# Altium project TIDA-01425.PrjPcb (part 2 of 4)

## Sheet DIG PWR.SchDoc: DIG PWR
size 558 x 431 mm; Date: Not shown in title block; ApprovedBy: Not shown in title block; CheckedBy: Not shown in title block; Author: Not shown in title block; CompanyName: Not shown in title block; DrawnBy: Donovan Porter; Engineer: Not shown in title block; Organization: Not shown in title block; Address1: Not shown in title block; Address2: Not shown in title block; Address3: Not shown in title block; Address4: Not shown in title block; DocumentNumber: 5; Revision: Use project parameter SCH_Rev; SheetNumber: 5; SheetTotal: 12; PageSetup: Record=PageOptions¦CenterHorizontal=True¦CenterVertical=True¦PrintScale=1.00¦XCorrection=1.00¦YCorrection=1.00¦PrintKind=0¦BorderSize=5000000¦LeftOffset=0¦BottomOffset=0¦Orientation=2¦PaperLength=1000¦PaperWidth=1000¦Scale=100¦PaperSource=15¦PrintQuality=600¦MediaType=1¦DitherType=10¦PaperKind=Letter¦PrintScaleMode=1
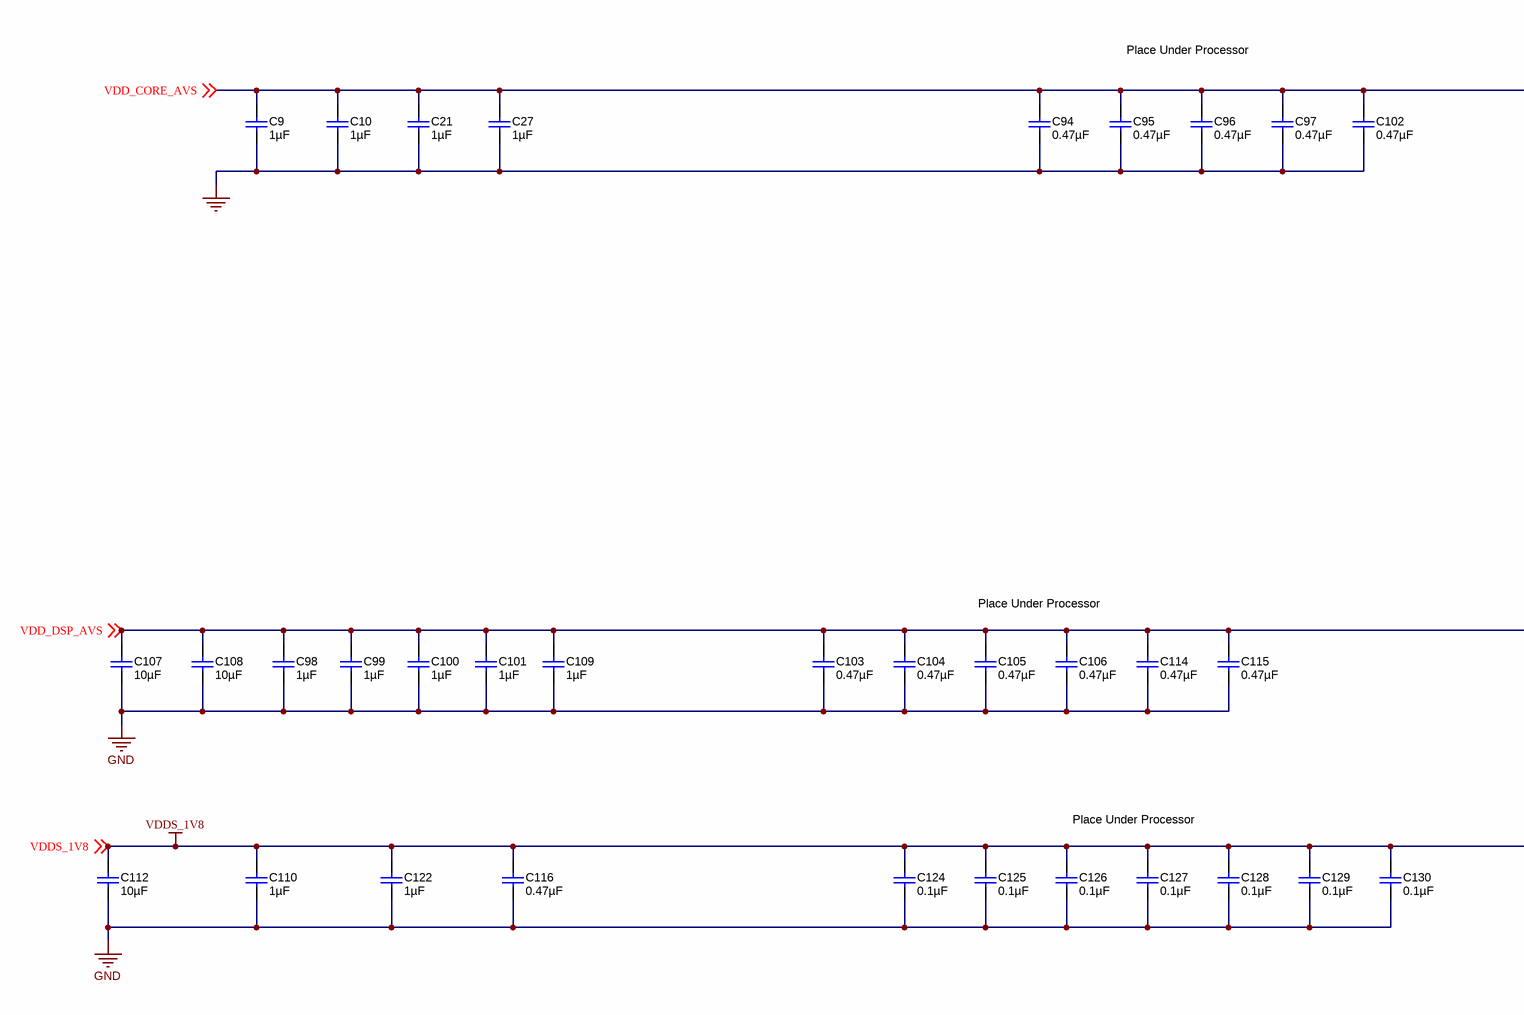
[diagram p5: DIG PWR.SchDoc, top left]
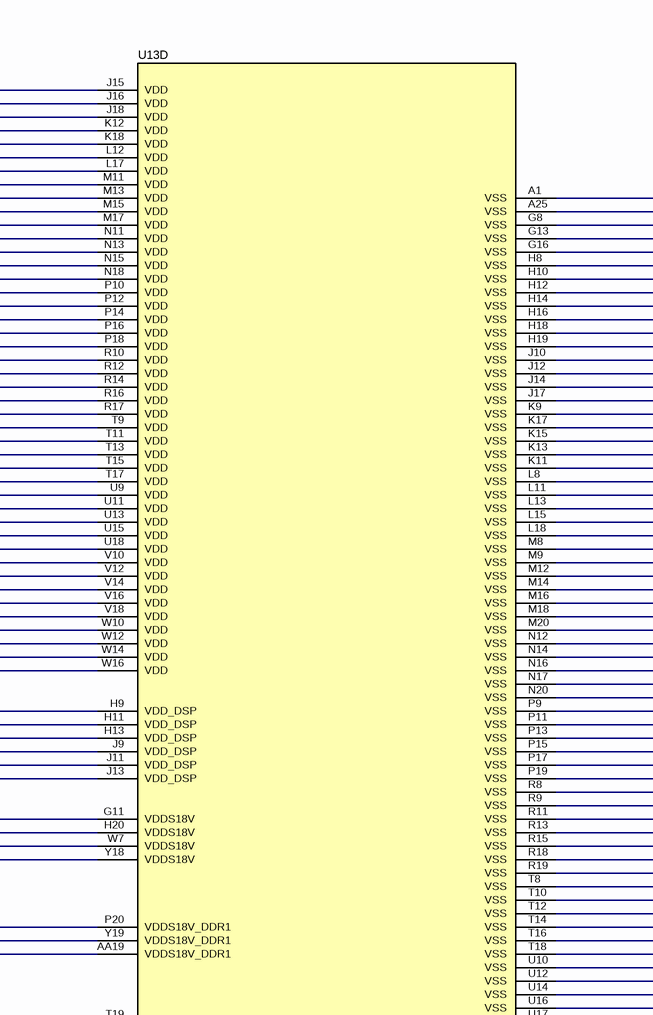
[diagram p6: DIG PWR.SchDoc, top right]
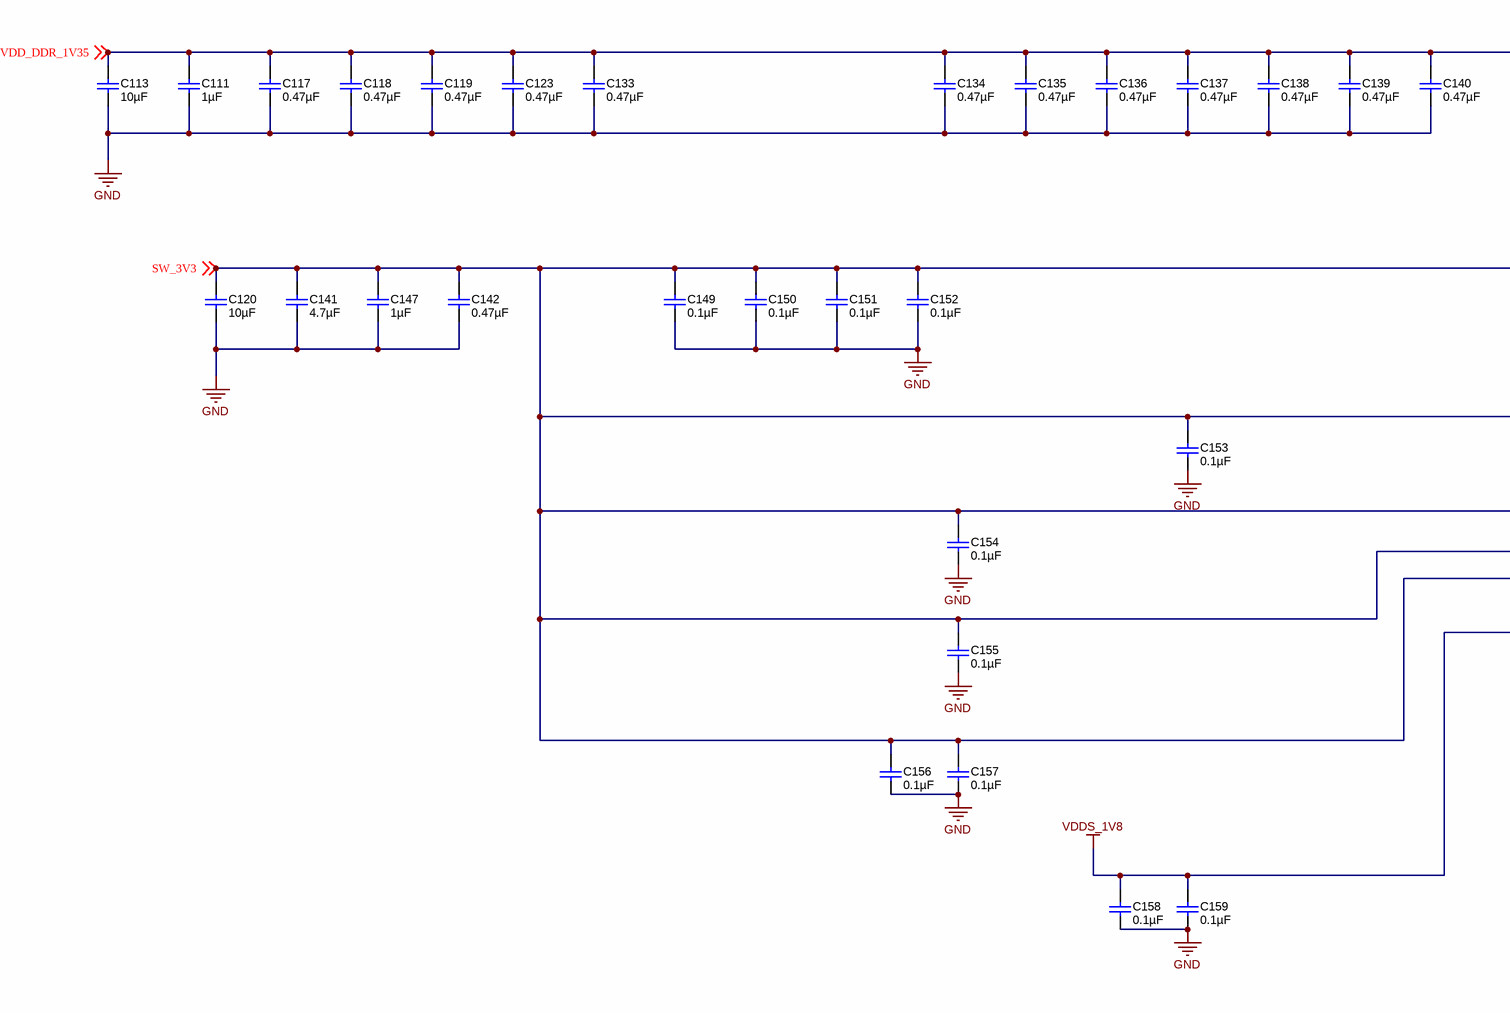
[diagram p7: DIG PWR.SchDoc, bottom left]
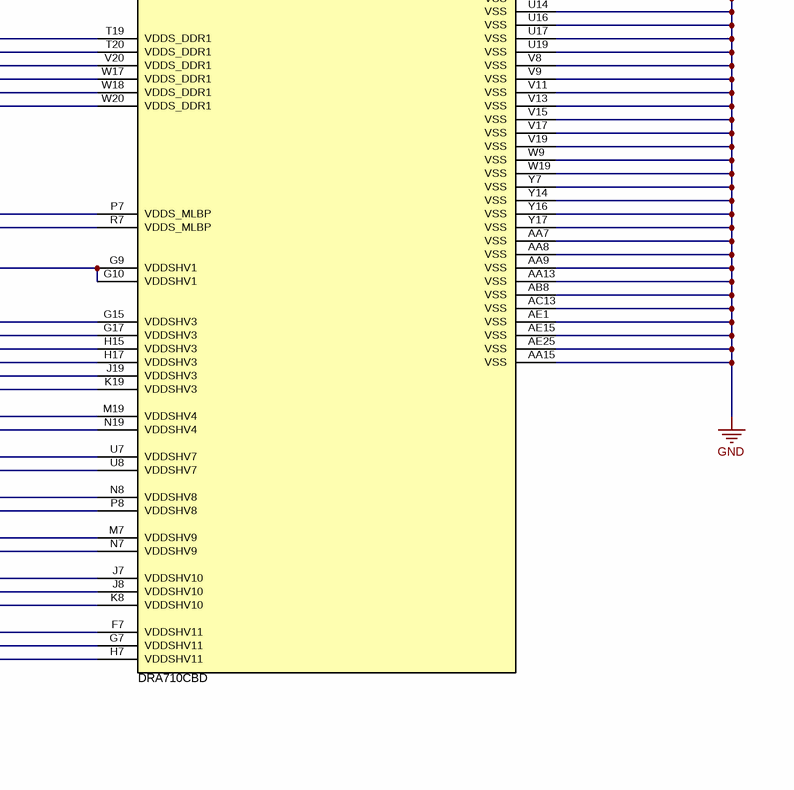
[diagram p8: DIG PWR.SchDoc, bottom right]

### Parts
C9  ValueDisplayed: 1µF  [0508]  (hidden comment: LLL219R70J105MA01L)
C10  ValueDisplayed: 1µF  [0508]  (hidden comment: LLL219R70J105MA01L)
C21  ValueDisplayed: 1µF  [0508]  (hidden comment: LLL219R70J105MA01L)
C27  ValueDisplayed: 1µF  [0508]  (hidden comment: LLL219R70J105MA01L)
C94  ValueDisplayed: 0.47µF  [0402L]  (hidden comment: GCM155C71A474KE36D)
C95  ValueDisplayed: 0.47µF  [0402L]  (hidden comment: GCM155C71A474KE36D)
C96  ValueDisplayed: 0.47µF  [0402L]  (hidden comment: GCM155C71A474KE36D)
C97  ValueDisplayed: 0.47µF  [0402L]  (hidden comment: GCM155C71A474KE36D)
C98  ValueDisplayed: 1µF  [0508]  (hidden comment: LLL219R70J105MA01L)
C99  ValueDisplayed: 1µF  [0508]  (hidden comment: LLL219R70J105MA01L)
C100  ValueDisplayed: 1µF  [0508]  (hidden comment: LLL219R70J105MA01L)
C101  ValueDisplayed: 1µF  [0508]  (hidden comment: LLL219R70J105MA01L)
C102  ValueDisplayed: 0.47µF  [0402L]  (hidden comment: GCM155C71A474KE36D)
C103  ValueDisplayed: 0.47µF  [0402L]  (hidden comment: GCM155C71A474KE36D)
C104  ValueDisplayed: 0.47µF  [0402L]  (hidden comment: GCM155C71A474KE36D)
C105  ValueDisplayed: 0.47µF  [0402L]  (hidden comment: GCM155C71A474KE36D)
C106  ValueDisplayed: 0.47µF  [0402L]  (hidden comment: GCM155C71A474KE36D)
C107  ValueDisplayed: 10µF  [0805_HV]  (hidden comment: GCM21BR71A106KE22L)
C108  ValueDisplayed: 10µF  [0805_HV]  (hidden comment: GCM21BR71A106KE22L)
C109  ValueDisplayed: 1µF  [0508]  (hidden comment: LLL219R70J105MA01L)
C110  ValueDisplayed: 1µF  [0508]  (hidden comment: LLL219R70J105MA01L)
C111  ValueDisplayed: 1µF  [0508]  (hidden comment: LLL219R70J105MA01L)
C112  ValueDisplayed: 10µF  [0805_HV]  (hidden comment: GCM21BR71A106KE22L)
C113  ValueDisplayed: 10µF  [0805_HV]  (hidden comment: GCM21BR71A106KE22L)
C114  ValueDisplayed: 0.47µF  [0402L]  (hidden comment: GCM155C71A474KE36D)
C115  ValueDisplayed: 0.47µF  [0402L]  (hidden comment: GCM155C71A474KE36D)
C116  ValueDisplayed: 0.47µF  [0402]  (hidden comment: GCM155C71A474KE36D)
C117  ValueDisplayed: 0.47µF  [0402L]  (hidden comment: GCM155C71A474KE36D)
C118  ValueDisplayed: 0.47µF  [0402L]  (hidden comment: GCM155C71A474KE36D)
C119  ValueDisplayed: 0.47µF  [0402L]  (hidden comment: GCM155C71A474KE36D)
C120  ValueDisplayed: 10µF  [0805_HV]  (hidden comment: GCM21BR71A106KE22L)
C122  ValueDisplayed: 1µF  [0402]  (hidden comment: C1005X7S1A105K050BC)
C123  ValueDisplayed: 0.47µF  [0402L]  (hidden comment: GCM155C71A474KE36D)
C124  ValueDisplayed: 0.1µF  [0402L]  (hidden comment: GRM155R71C104KA88D)
C125  ValueDisplayed: 0.1µF  [0402L]  (hidden comment: GRM155R71C104KA88D)
C126  ValueDisplayed: 0.1µF  [0402L]  (hidden comment: GRM155R71C104KA88D)
C127  ValueDisplayed: 0.1µF  [0402L]  (hidden comment: GRM155R71C104KA88D)
C128  ValueDisplayed: 0.1µF  [0402L]  (hidden comment: GRM155R71C104KA88D)
C129  ValueDisplayed: 0.1µF  [0402L]  (hidden comment: GRM155R71C104KA88D)
C130  ValueDisplayed: 0.1µF  [0402L]  (hidden comment: GRM155R71C104KA88D)
C133  ValueDisplayed: 0.47µF  [0402L]  (hidden comment: GCM155C71A474KE36D)
C134  ValueDisplayed: 0.47µF  [0402L]  (hidden comment: GCM155C71A474KE36D)
C135  ValueDisplayed: 0.47µF  [0402L]  (hidden comment: GCM155C71A474KE36D)
C136  ValueDisplayed: 0.47µF  [0402L]  (hidden comment: GCM155C71A474KE36D)
C137  ValueDisplayed: 0.47µF  [0402L]  (hidden comment: GCM155C71A474KE36D)
C138  ValueDisplayed: 0.47µF  [0402L]  (hidden comment: GCM155C71A474KE36D)
C139  ValueDisplayed: 0.47µF  [0402L]  (hidden comment: GCM155C71A474KE36D)
C140  ValueDisplayed: 0.47µF  [0402L]  (hidden comment: GCM155C71A474KE36D)
C141  ValueDisplayed: 4.7µF  [0805_HV]  (hidden comment: GRM21BR71C475KA73L)
C142  ValueDisplayed: 0.47µF  [0402L]  (hidden comment: GCM155C71A474KE36D)
C147  ValueDisplayed: 1µF  [0402L]  (hidden comment: C1005X7S1A105K050BC)
C149  ValueDisplayed: 0.1µF  [0402L]  (hidden comment: GRM155R71C104KA88D)
C150  ValueDisplayed: 0.1µF  [0402L]  (hidden comment: GRM155R71C104KA88D)
C151  ValueDisplayed: 0.1µF  [0402L]  (hidden comment: GRM155R71C104KA88D)
C152  ValueDisplayed: 0.1µF  [0402L]  (hidden comment: GRM155R71C104KA88D)
C153  ValueDisplayed: 0.1µF  [0402L]  (hidden comment: GRM155R71C104KA88D)
C154  ValueDisplayed: 0.1µF  [0402L]  (hidden comment: GRM155R71C104KA88D)
C155  ValueDisplayed: 0.1µF  [0402L]  (hidden comment: GRM155R71C104KA88D)
C156  ValueDisplayed: 0.1µF  [0402L]  (hidden comment: GRM155R71C104KA88D)
C157  ValueDisplayed: 0.1µF  [0402L]  (hidden comment: GRM155R71C104KA88D)
C158  ValueDisplayed: 0.1µF  [0402]  (hidden comment: GRM155R71C104KA88D)
C159  ValueDisplayed: 0.1µF  [0402]  (hidden comment: GRM155R71C104KA88D)
U13  DRA710CBD  [CBD0538A]  (part D of 5)

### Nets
GND: C9.2 C10.2 C21.2 C27.2 C94.2 C95.2 C96.2 C97.2 C98.2 C99.2 C100.2 C101.2 C102.2 C103.2 C104.2 C105.2 C106.2 C107.2 C108.2 C109.2 C110.2 C111.2 C112.2 C113.2 C114.2 C115.2 C116.2 C117.2 C118.2 C119.2 C120.2 C122.2 C123.2 C124.2 C125.2 C126.2 C127.2 C128.2 C129.2 C130.2 C133.2 C134.2 C135.2 C136.2 C137.2 C138.2 C139.2 C140.2 C141.2 C142.2 C147.2 C149.2 C150.2 C151.2 C152.2 C153.2 C154.2 C155.2 C156.2 C157.2 C158.2 C159.2 U13.A1(VSS) U13.A25(VSS) U13.AA7(VSS) U13.AA8(VSS) U13.AA9(VSS) U13.AA13(VSS) U13.AA15(VSS) U13.AB8(VSS) U13.AC13(VSS) U13.AE1(VSS) U13.AE15(VSS) U13.AE25(VSS) U13.G8(VSS) U13.G13(VSS) U13.G16(VSS) U13.H8(VSS) U13.H10(VSS) U13.H12(VSS) U13.H14(VSS) U13.H16(VSS) U13.H18(VSS) U13.H19(VSS) U13.J10(VSS) U13.J12(VSS) U13.J14(VSS) U13.J17(VSS) U13.K9(VSS) U13.K11(VSS) U13.K13(VSS) U13.K15(VSS) U13.K17(VSS) U13.L8(VSS) U13.L11(VSS) U13.L13(VSS) U13.L15(VSS) U13.L18(VSS) U13.M8(VSS) U13.M9(VSS) U13.M12(VSS) U13.M14(VSS) U13.M16(VSS) U13.M18(VSS) U13.M20(VSS) U13.N12(VSS) U13.N14(VSS) U13.N16(VSS) U13.N17(VSS) U13.N20(VSS) U13.P9(VSS) U13.P11(VSS) U13.P13(VSS) U13.P15(VSS) U13.P17(VSS) U13.P19(VSS) U13.R8(VSS) U13.R9(VSS) U13.R11(VSS) U13.R13(VSS) U13.R15(VSS) U13.R18(VSS) U13.R19(VSS) U13.T8(VSS) U13.T10(VSS) U13.T12(VSS) U13.T14(VSS) U13.T16(VSS) U13.T18(VSS) U13.U10(VSS) U13.U12(VSS) U13.U14(VSS) U13.U16(VSS) U13.U17(VSS) U13.U19(VSS) U13.V8(VSS) U13.V9(VSS) U13.V11(VSS) U13.V13(VSS) U13.V15(VSS) U13.V17(VSS) U13.V19(VSS) U13.W9(VSS) U13.W19(VSS) U13.Y7(VSS) U13.Y14(VSS) U13.Y16(VSS) U13.Y17(VSS)
VDDS_1V8: C110.1 C112.1 C116.1 C122.1 C124.1 C125.1 C126.1 C127.1 C128.1 C129.1 C130.1 C158.1 C159.1 U13.AA19(VDDS18V_DDR1) U13.F7(VDDSHV11) U13.G7(VDDSHV11) U13.G11(VDDS18V) U13.H7(VDDSHV11) U13.H20(VDDS18V) U13.P7(VDDS_MLBP) U13.P20(VDDS18V_DDR1) U13.R7(VDDS_MLBP) U13.W7(VDDS18V) U13.Y18(VDDS18V) U13.Y19(VDDS18V_DDR1) ; off-sheet VDDS_1V8
SW_3V3: C120.1 C141.1 C142.1 C147.1 C149.1 C150.1 C151.1 C152.1 C153.1 C154.1 C155.1 C156.1 C157.1 U13.G9(VDDSHV1) U13.G10(VDDSHV1) U13.G15(VDDSHV3) U13.G17(VDDSHV3) U13.H15(VDDSHV3) U13.H17(VDDSHV3) U13.J7(VDDSHV10) U13.J8(VDDSHV10) U13.J19(VDDSHV3) U13.K8(VDDSHV10) U13.K19(VDDSHV3) U13.M7(VDDSHV9) U13.M19(VDDSHV4) U13.N7(VDDSHV9) U13.N8(VDDSHV8) U13.N19(VDDSHV4) U13.P8(VDDSHV8) U13.U7(VDDSHV7) U13.U8(VDDSHV7) ; off-sheet SW_3V3
VDD_CORE_AVS: C9.1 C10.1 C21.1 C27.1 C94.1 C95.1 C96.1 C97.1 C102.1 U13.J15(VDD) U13.J16(VDD) U13.J18(VDD) U13.K12(VDD) U13.K18(VDD) U13.L12(VDD) U13.L17(VDD) U13.M11(VDD) U13.M13(VDD) U13.M15(VDD) U13.M17(VDD) U13.N11(VDD) U13.N13(VDD) U13.N15(VDD) U13.N18(VDD) U13.P10(VDD) U13.P12(VDD) U13.P14(VDD) U13.P16(VDD) U13.P18(VDD) U13.R10(VDD) U13.R12(VDD) U13.R14(VDD) U13.R16(VDD) U13.R17(VDD) U13.T9(VDD) U13.T11(VDD) U13.T13(VDD) U13.T15(VDD) U13.T17(VDD) U13.U9(VDD) U13.U11(VDD) U13.U13(VDD) U13.U15(VDD) U13.U18(VDD) U13.V10(VDD) U13.V12(VDD) U13.V14(VDD) U13.V16(VDD) U13.V18(VDD) U13.W10(VDD) U13.W12(VDD) U13.W14(VDD) U13.W16(VDD) ; off-sheet VDD_CORE_AVS
VDD_DDR_1V35: C111.1 C113.1 C117.1 C118.1 C119.1 C123.1 C133.1 C134.1 C135.1 C136.1 C137.1 C138.1 C139.1 C140.1 U13.T19(VDDS_DDR1) U13.T20(VDDS_DDR1) U13.V20(VDDS_DDR1) U13.W17(VDDS_DDR1) U13.W18(VDDS_DDR1) U13.W20(VDDS_DDR1) ; off-sheet VDD_DDR_1V35
VDD_DSP_AVS: C98.1 C99.1 C100.1 C101.1 C103.1 C104.1 C105.1 C106.1 C107.1 C108.1 C109.1 C114.1 C115.1 U13.H9(VDD_DSP) U13.H11(VDD_DSP) U13.H13(VDD_DSP) U13.J9(VDD_DSP) U13.J11(VDD_DSP) U13.J13(VDD_DSP) ; off-sheet VDD_DSP_AVS

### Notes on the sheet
- Place Under Processor

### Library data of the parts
C9 C10 C21 C27 C98-C101 C109-C111 = LLL219R70J105MA01L: CAP, CERM, 1 µF, 6.3 V, +/- 20%, X7R, 0508; Manufacturer: MuRata; Polarized: N; CompType: Capacitor; Value: 1uF; U/M: EA; Cap_F: 0.000001; Tolerance_%: 20; Value1: Unknown; VDC_V: 6.3; Value2: 6.3V; TaMin_C: -55; TaMax_C: 125; SizeArea_mm2: 2.5; SizeAreaWB_mm2: 6.75; SizeX_mm: 1.25; SizeY_mm: 2; SizeZ_mm: 1; AEC Category: Q200
C94-C97 C102-C106 C114 C115 C117-C119 C123 C133-C140 C142 = GCM155C71A474KE36D: CAP, CERM, 0.47 µF, 10 V, +/- 10%, X7S, 0402; Manufacturer: MuRata; Polarized: N; CompType: Capacitor; Value: 0.47uF; U/M: EA; Cap_F: 0.00000047; Tolerance_%: 10; Value1: Unknown; Value2: 10V; TaMin_C: -55; TaMax_C: 125; Cap_Case: 0402; SizeArea_mm2: 0.5; SizeAreaWB_mm2: 3; SizeX_mm: 1; SizeZ_mm: 0.6; AEC Category: Q200
C107 C108 C112 C113 C120 = GCM21BR71A106KE22L: CAP, CERM, 10 µF, 10 V, +/- 10%, X7R, 0805; Manufacturer: MuRata; Polarized: N; CompType: Capacitor; Value: 10uF; U/M: EA; Cap_F: 0.00001; Tolerance_%: 10; Value1: Unknown; Value2: 10V; TaMin_C: -55; TaMax_C: 125; Cap_Case: 0805; SizeArea_mm2: 2.5; SizeAreaWB_mm2: 6.75; SizeX_mm: 2; SizeY_mm: 1.25; SizeZ_mm: 1.45; AEC Category: Q200
C116 = GCM155C71A474KE36D: CAP, CERM, 0.47 µF, 10 V, +/- 10%, X7S, 0402; Manufacturer: MuRata; Polarized: N; CompType: Capacitor; Value: 0.47uF; U/M: EA; Cap_F: 0.00000047; Tolerance_%: 10; Value1: Unknown; Value2: 10V; TaMin_C: -55; TaMax_C: 125; SizeArea_mm2: 0.5; SizeAreaWB_mm2: 3; SizeX_mm: 1; SizeZ_mm: 0.6; AEC Category: Q200
C122 = C1005X7S1A105K050BC: CAP, CERM, 1 µF, 10 V, +/- 10%, X7S, 0402; Manufacturer: TDK; Polarized: N; CompType: Capacitor; Value: 1uF; U/M: EA; Cap_F: 0.000001; Tolerance_%: 10; ESR_ohm: 0.011416; Value1: 0.011416 ohm; Value2: 10V; IRMS_A: 1.483; TaMin_C: -55; TaMax_C: 125; SizeArea_mm2: 0.5; SizeAreaWB_mm2: 3; SizeX_mm: 1; SizeZ_mm: 0.6; AEC Category: Q200
C124-C130 C149-C157 = GRM155R71C104KA88D: CAP, CERM, 0.1 µF, 16 V, +/- 10%, X7R, 0402; Manufacturer: MuRata; Polarized: N; CompType: Capacitor; Value: 0.1uF; U/M: EA; Cap_F: 0.0000001; Tolerance_%: 10; Value1: Unknown; VDC_V: 16; Value2: 16V; TaMin_C: -55; TaMax_C: 125; Cap_Case: 0402; SizeArea_mm2: 0.5; SizeAreaWB_mm2: 3; SizeX_mm: 1; SizeZ_mm: 0.6; AEC Category: Q200
C141 = GRM21BR71C475KA73L: CAP, CERM, 4.7 µF, 16 V, +/- 10%, X7R, 0805; Manufacturer: MuRata; Polarized: N; CompType: Capacitor; Value: 4.7uF; U/M: EA; Cap_F: 0.0000047; Tolerance_%: 10; ESR_ohm: 0.006; Value1: 0.006 ohm; VDC_V: 16; Value2: 16V; TaMin_C: -55; TaMax_C: 125; Cap_Case: 0805; SizeArea_mm2: 2.5; SizeAreaWB_mm2: 6.75; SizeX_mm: 2; SizeY_mm: 1.25; SizeZ_mm: 1.45; AEC Category: Q200
C147 = C1005X7S1A105K050BC: CAP, CERM, 1 µF, 10 V, +/- 10%, X7S, 0402; Manufacturer: TDK; Polarized: N; CompType: Capacitor; Value: 1uF; U/M: EA; Cap_F: 0.000001; Tolerance_%: 10; ESR_ohm: 0.011416; Value1: 0.011416 ohm; Value2: 10V; IRMS_A: 1.483; TaMin_C: -55; TaMax_C: 125; Cap_Case: 0402; SizeArea_mm2: 0.5; SizeAreaWB_mm2: 3; SizeX_mm: 1; SizeZ_mm: 0.6; AEC Category: Q200
C158 C159 = GRM155R71C104KA88D: CAP, CERM, 0.1 µF, 16 V, +/- 10%, X7R, 0402; Manufacturer: MuRata; Polarized: N; CompType: Capacitor; Value: 0.1uF; U/M: EA; Cap_F: 0.0000001; Tolerance_%: 10; Value1: Unknown; VDC_V: 16; Value2: 16V; TaMin_C: -55; TaMax_C: 125; SizeArea_mm2: 0.5; SizeAreaWB_mm2: 3; SizeX_mm: 1; SizeZ_mm: 0.6; AEC Category: Q200
U13 = DRA710CBD: Infotainment Applications Processor, CBD0538A (BGA-538); Manufacturer: Texas Instruments; SymbolCreator: Altium; SizeArea_mm2: 289; SizeAreaWB_mm2: 361; SizeX_mm: 17; SizeZ_mm: 1.298; CompType: IC; U/M: EA

## Sheet J6Entry.SchDoc: J6Entry
size 558 x 431 mm; Date: Not shown in title block; ApprovedBy: Not shown in title block; CheckedBy: Not shown in title block; Author: Not shown in title block; CompanyName: Not shown in title block; DrawnBy: Donovan Porter; Engineer: Not shown in title block; Organization: Not shown in title block; Address1: Not shown in title block; Address2: Not shown in title block; Address3: Not shown in title block; Address4: Not shown in title block; DocumentNumber: 10; Revision: Use project parameter SCH_Rev; SheetNumber: 10; SheetTotal: 12; PageSetup: Record=PageOptions¦CenterHorizontal=True¦CenterVertical=True¦PrintScale=1.00¦XCorrection=1.00¦YCorrection=1.00¦PrintKind=0¦BorderSize=5000000¦LeftOffset=0¦BottomOffset=0¦Orientation=2¦PaperLength=1000¦PaperWidth=1000¦Scale=100¦PaperSource=15¦PrintQuality=600¦MediaType=1¦DitherType=10¦PaperKind=Letter¦PrintScaleMode=1
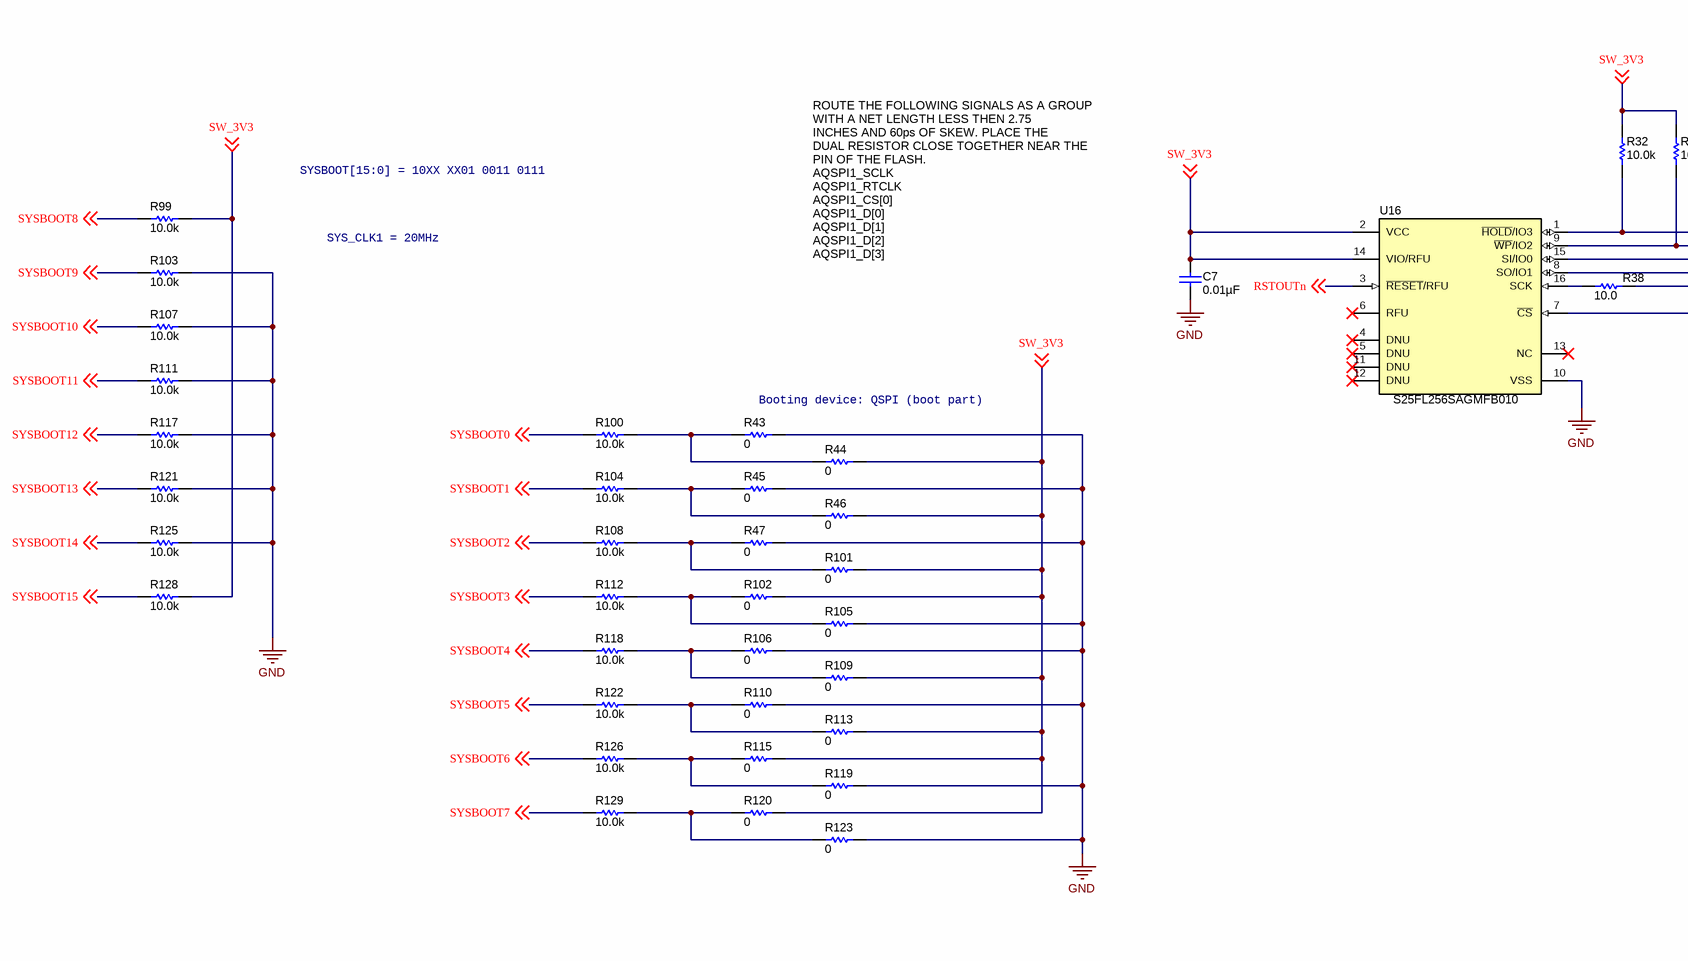
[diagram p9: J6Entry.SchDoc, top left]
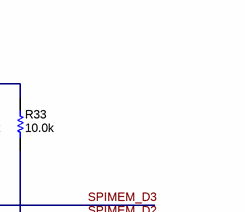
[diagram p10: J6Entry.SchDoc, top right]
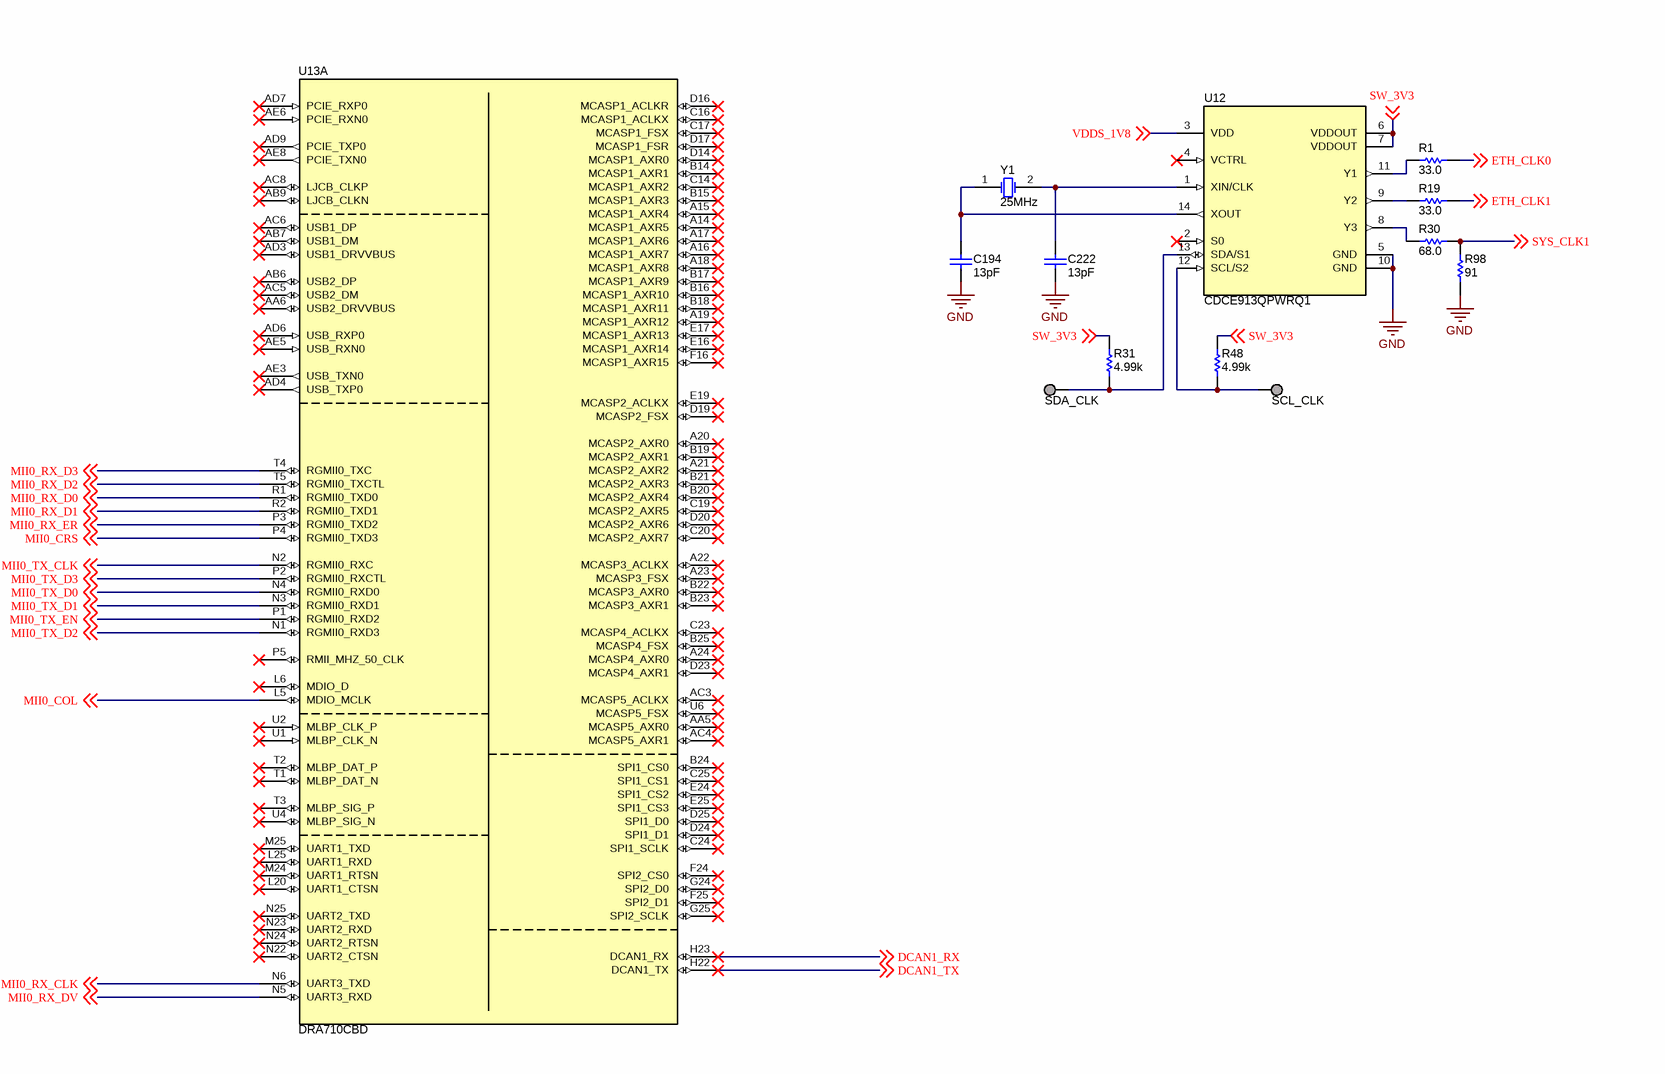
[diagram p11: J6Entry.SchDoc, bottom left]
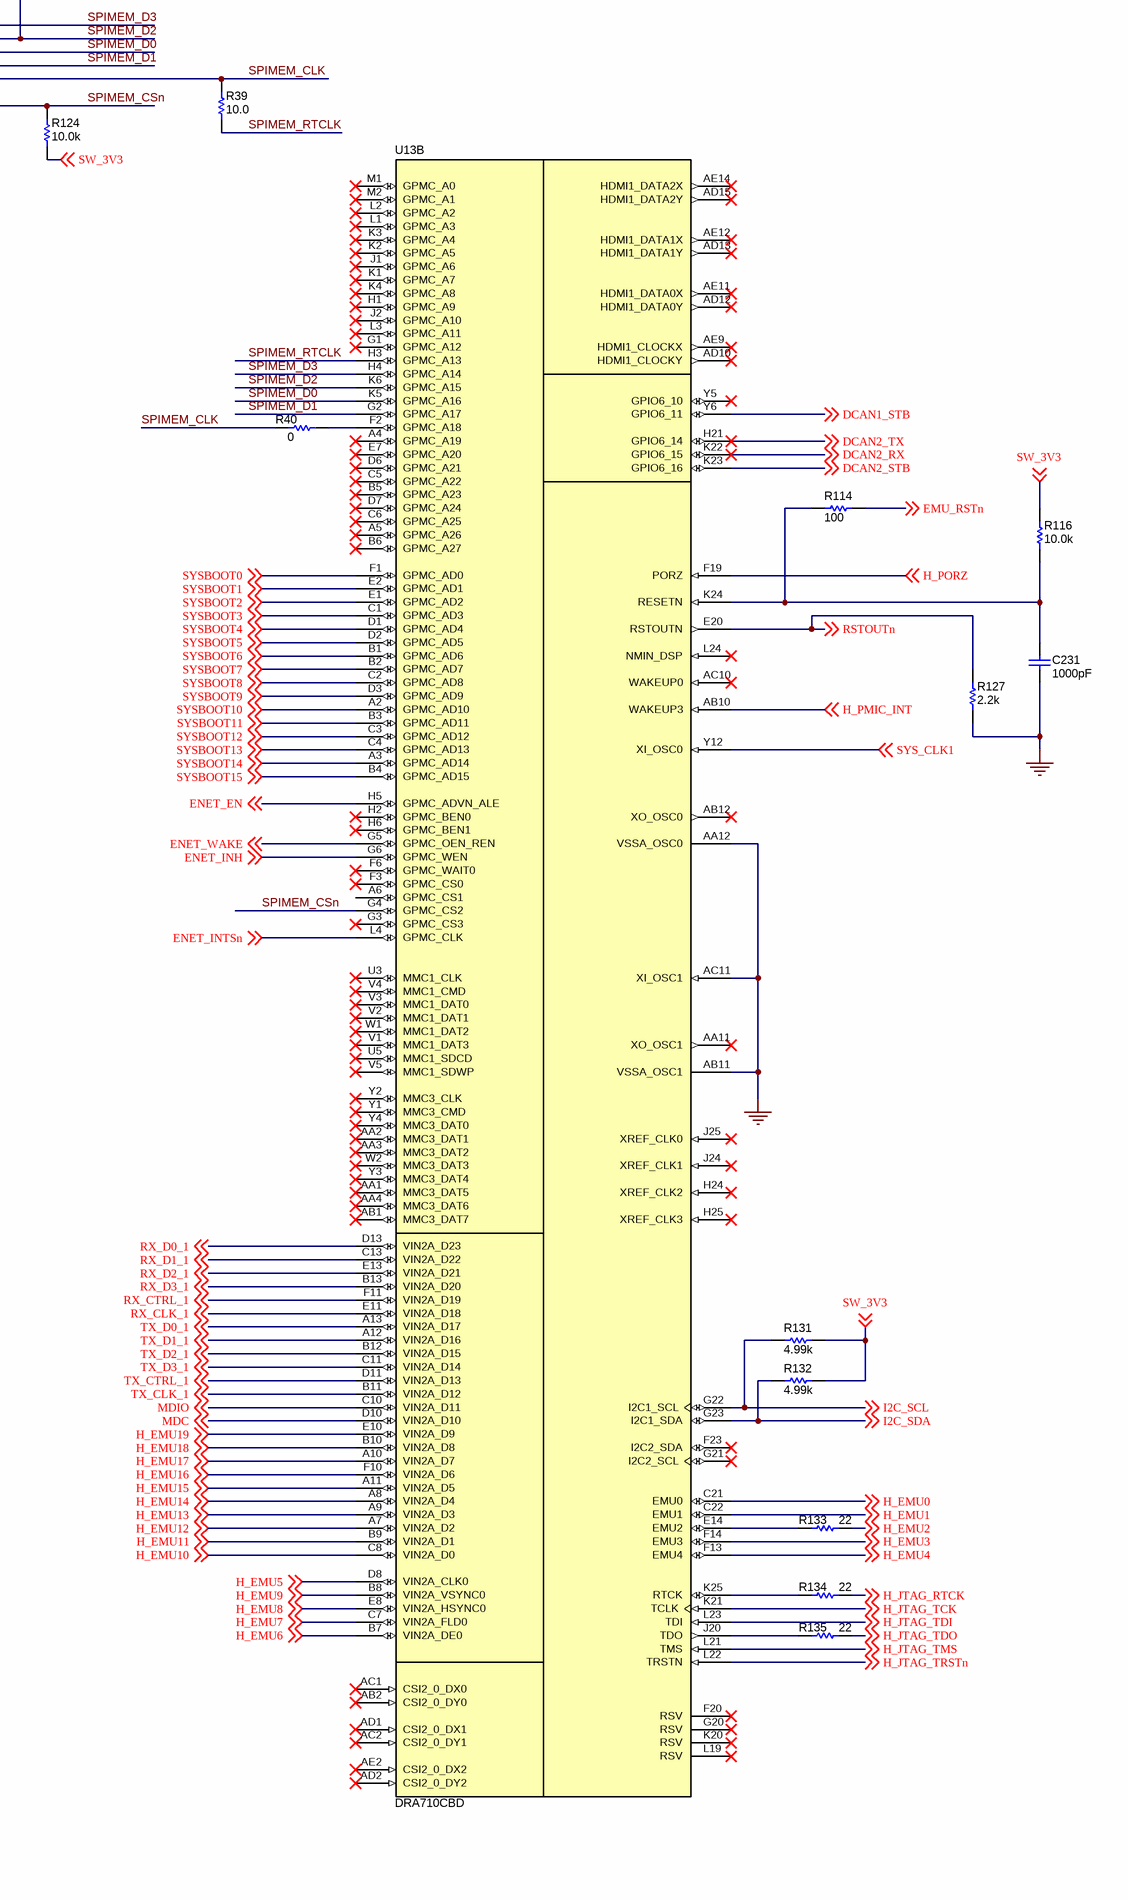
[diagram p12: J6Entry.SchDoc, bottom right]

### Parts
C7  ValueDisplayed: 0.01µF  [0402L]  (hidden comment: 0402ZC103KAT2A)
C194  ValueDisplayed: 13pF  [0603]  (hidden comment: GRM1885C1H130JA01D)
C222  ValueDisplayed: 13pF  [0603]  (hidden comment: GRM1885C1H130JA01D)
C231  ValueDisplayed: 1000pF  [0201_033]  (hidden comment: CGA1A2X7R1E102K030BA)
R1  ValueDisplayed: 33.0  [0603]  (hidden comment: RC0603FR-0733RL)
R19  ValueDisplayed: 33.0  [0603]  (hidden comment: RC0603FR-0733RL)
R30  ValueDisplayed: 68.0  [0603]  (hidden comment: RC0603FR-0768RL)
R31  ValueDisplayed: 4.99k  [0201]  (hidden comment: RC0201FR-074K99L)
R32  ValueDisplayed: 10.0k  [0603L]  (hidden comment: RCG060310K0FKEA)
R33  ValueDisplayed: 10.0k  [0603L]  (hidden comment: RCG060310K0FKEA)
R38  ValueDisplayed: 10.0  [0603L]  (hidden comment: CRCW060310R0FKEA)
R39  ValueDisplayed: 10.0  [0603L]  (hidden comment: CRCW060310R0FKEA)
R40  ValueDisplayed: 0  [0603]  (hidden comment: ERJ-3GEY0R00V)
R43  ValueDisplayed: 0  [0603L]  (hidden comment: RMCF0603ZT0R00)
R44  ValueDisplayed: 0  [0603L]  (hidden comment: RMCF0603ZT0R00)
R45  ValueDisplayed: 0  [0603L]  (hidden comment: RMCF0603ZT0R00)
R46  ValueDisplayed: 0  [0603L]  (hidden comment: RMCF0603ZT0R00)
R47  ValueDisplayed: 0  [0603L]  (hidden comment: RMCF0603ZT0R00)
R48  ValueDisplayed: 4.99k  [0201]  (hidden comment: RC0201FR-074K99L)
R98  ValueDisplayed: 91  [0603]  (hidden comment: CRCW060391R0JNEA)
R99  ValueDisplayed: 10.0k  [0201]  (hidden comment: CRCW020110K0FKED)
R100  ValueDisplayed: 10.0k  [0201]  (hidden comment: CRCW020110K0FKED)
R101  ValueDisplayed: 0  [0603L]  (hidden comment: RMCF0603ZT0R00)
R102  ValueDisplayed: 0  [0603L]  (hidden comment: RMCF0603ZT0R00)
R103  ValueDisplayed: 10.0k  [0201]  (hidden comment: CRCW020110K0FKED)
R104  ValueDisplayed: 10.0k  [0201]  (hidden comment: CRCW020110K0FKED)
R105  ValueDisplayed: 0  [0603L]  (hidden comment: RMCF0603ZT0R00)
R106  ValueDisplayed: 0  [0603L]  (hidden comment: RMCF0603ZT0R00)
R107  ValueDisplayed: 10.0k  [0201]  (hidden comment: CRCW020110K0FKED)
R108  ValueDisplayed: 10.0k  [0201]  (hidden comment: CRCW020110K0FKED)
R109  ValueDisplayed: 0  [0603L]  (hidden comment: RMCF0603ZT0R00)
R110  ValueDisplayed: 0  [0603L]  (hidden comment: RMCF0603ZT0R00)
R111  ValueDisplayed: 10.0k  [0201]  (hidden comment: CRCW020110K0FKED)
R112  ValueDisplayed: 10.0k  [0201]  (hidden comment: CRCW020110K0FKED)
R113  ValueDisplayed: 0  [0603L]  (hidden comment: RMCF0603ZT0R00)
R114  ValueDisplayed: 100  [0201]  (hidden comment: RC0201FR-07100RL)
R115  ValueDisplayed: 0  [0603L]  (hidden comment: RMCF0603ZT0R00)
R116  ValueDisplayed: 10.0k  [0201]  (hidden comment: CRCW020110K0FKED)
R117  ValueDisplayed: 10.0k  [0201]  (hidden comment: CRCW020110K0FKED)
R118  ValueDisplayed: 10.0k  [0201]  (hidden comment: CRCW020110K0FKED)
R119  ValueDisplayed: 0  [0603L]  (hidden comment: RMCF0603ZT0R00)
R120  ValueDisplayed: 0  [0603L]  (hidden comment: RMCF0603ZT0R00)
R121  ValueDisplayed: 10.0k  [0201]  (hidden comment: CRCW020110K0FKED)
R122  ValueDisplayed: 10.0k  [0201]  (hidden comment: CRCW020110K0FKED)
R123  ValueDisplayed: 0  [0603L]  (hidden comment: RMCF0603ZT0R00)
R124  ValueDisplayed: 10.0k  [0603L]  (hidden comment: RCG060310K0FKEA)
R125  ValueDisplayed: 10.0k  [0201]  (hidden comment: CRCW020110K0FKED)
R126  ValueDisplayed: 10.0k  [0201]  (hidden comment: CRCW020110K0FKED)
R127  ValueDisplayed: 2.2k  [0201]  (hidden comment: RC0201JR-072K2L)
R128  ValueDisplayed: 10.0k  [0201]  (hidden comment: CRCW020110K0FKED)
R129  ValueDisplayed: 10.0k  [0201]  (hidden comment: CRCW020110K0FKED)
R131  ValueDisplayed: 4.99k  [0201]  (hidden comment: RC0201FR-074K99L)
R132  ValueDisplayed: 4.99k  [0201]  (hidden comment: RC0201FR-074K99L)
R133  ValueDisplayed: 22  [0402]  (hidden comment: CRCW040222R0JNED)
R134  ValueDisplayed: 22  [0402]  (hidden comment: CRCW040222R0JNED)
R135  ValueDisplayed: 22  [0402]  (hidden comment: CRCW040222R0JNED)
SCL_CLK  TESTPOINT  [PAD_3-2x1-9MM_SMD]  (value not drawn)  (no BOM)
SDA_CLK  TESTPOINT  [PAD_3-2x1-9MM_SMD]  (value not drawn)  (no BOM)
U12  CDCE913QPWRQ1  [PW0014A_N]
U13  DRA710CBD  [CBD0538A]  (parts A,B of 5)
U16  S25FL256SAGMFB010  [SOIC-16]
Y1  Frequency: 25MHz  [NDK_NX5032GA]  (hidden comment: NX5032GA-25.000M-STD-CSK-4)

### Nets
GND: C7.2 C194.2 C222.2 C231.2 R43.2 R45.2 R47.2 R98.1 R103.1 R105.2 R106.2 R107.1 R110.2 R111.1 R117.1 R119.2 R121.1 R123.2 R125.1 R127.1 U12.5(GND) U12.10(GND) U13.AA12(VSSA_OSC0) U13.AB11(VSSA_OSC1) U13.AC11(XI_OSC1) U16.10(VSS)
VDDS_1V8: U12.3(VDD) ; off-sheet VDDS_1V8
DCAN1_RX: U13.H23(DCAN1_RX) ; off-sheet DCAN1_RX
DCAN1_STB: U13.Y6(GPIO6_11) ; off-sheet DCAN1_STB
DCAN1_TX: U13.H22(DCAN1_TX) ; off-sheet DCAN1_TX
DCAN2_RX: U13.K22(GPIO6_15) ; off-sheet DCAN2_RX
DCAN2_STB: U13.K23(GPIO6_16) ; off-sheet DCAN2_STB
DCAN2_TX: U13.H21(GPIO6_14) ; off-sheet DCAN2_TX
EMU_RSTn: R114.1 ; off-sheet EMU_RSTn
ENET_EN: U13.H5(GPMC_ADVN_ALE) ; off-sheet ENET_EN
ENET_INH: U13.G6(GPMC_WEN) ; off-sheet ENET_INH
ENET_INTSn: U13.L4(GPMC_CLK) ; off-sheet ENET_INTSn
ENET_WAKE: U13.G5(GPMC_OEN_REN) ; off-sheet ENET_WAKE
ETH_CLK0: R1.2 ; off-sheet ETH_CLK0
ETH_CLK1: R19.2 ; off-sheet ETH_CLK1
H_EMU0: U13.C21(EMU0) ; off-sheet H_EMU0
H_EMU1: U13.C22(EMU1) ; off-sheet H_EMU1
H_EMU2: R133.2 ; off-sheet H_EMU2
H_EMU3: U13.F14(EMU3) ; off-sheet H_EMU3
H_EMU4: U13.F13(EMU4) ; off-sheet H_EMU4
H_EMU5: U13.D8(VIN2A_CLK0) ; off-sheet H_EMU5
H_EMU6: U13.B7(VIN2A_DE0) ; off-sheet H_EMU6
H_EMU7: U13.C7(VIN2A_FLD0) ; off-sheet H_EMU7
H_EMU8: U13.E8(VIN2A_HSYNC0) ; off-sheet H_EMU8
H_EMU9: U13.B8(VIN2A_VSYNC0) ; off-sheet H_EMU9
H_EMU10: U13.C8(VIN2A_D0) ; off-sheet H_EMU10
H_EMU11: U13.B9(VIN2A_D1) ; off-sheet H_EMU11
H_EMU12: U13.A7(VIN2A_D2) ; off-sheet H_EMU12
H_EMU13: U13.A9(VIN2A_D3) ; off-sheet H_EMU13
H_EMU14: U13.A8(VIN2A_D4) ; off-sheet H_EMU14
H_EMU15: U13.A11(VIN2A_D5) ; off-sheet H_EMU15
H_EMU16: U13.F10(VIN2A_D6) ; off-sheet H_EMU16
H_EMU17: U13.A10(VIN2A_D7) ; off-sheet H_EMU17
H_EMU18: U13.B10(VIN2A_D8) ; off-sheet H_EMU18
H_EMU19: U13.E10(VIN2A_D9) ; off-sheet H_EMU19
H_JTAG_RTCK: R134.2 ; off-sheet H_JTAG_RTCK
H_JTAG_TCK: U13.K21(TCLK) ; off-sheet H_JTAG_TCK
H_JTAG_TDI: U13.L23(TDI) ; off-sheet H_JTAG_TDI
H_JTAG_TDO: R135.2 ; off-sheet H_JTAG_TDO
H_JTAG_TMS: U13.L21(TMS) ; off-sheet H_JTAG_TMS
H_JTAG_TRSTn: U13.L22(TRSTN) ; off-sheet H_JTAG_TRSTn
H_PMIC_INT: U13.AB10(WAKEUP3) ; off-sheet H_PMIC_INT
H_PORZ: U13.F19(PORZ) ; off-sheet H_PORZ
I2C_SCL: R131.1 U13.G22(I2C1_SCL) ; off-sheet I2C_SCL
I2C_SDA: R132.1 U13.G23(I2C1_SDA) ; off-sheet I2C_SDA
MDC: U13.D10(VIN2A_D10) ; off-sheet MDC
MDIO: U13.C10(VIN2A_D11) ; off-sheet MDIO
MII0_COL: U13.L5(MDIO_MCLK) ; off-sheet MII0_COL
MII0_CRS: U13.P4(RGMII0_TXD3) ; off-sheet MII0_CRS
MII0_RX_CLK: U13.N6(UART3_TXD) ; off-sheet MII0_RX_CLK
MII0_RX_D0: U13.R1(RGMII0_TXD0) ; off-sheet MII0_RX_D0
MII0_RX_D1: U13.R2(RGMII0_TXD1) ; off-sheet MII0_RX_D1
MII0_RX_D2: U13.T5(RGMII0_TXCTL) ; off-sheet MII0_RX_D2
MII0_RX_D3: U13.T4(RGMII0_TXC) ; off-sheet MII0_RX_D3
MII0_RX_DV: U13.N5(UART3_RXD) ; off-sheet MII0_RX_DV
MII0_RX_ER: U13.P3(RGMII0_TXD2) ; off-sheet MII0_RX_ER
MII0_TX_CLK: U13.N2(RGMII0_RXC) ; off-sheet MII0_TX_CLK
MII0_TX_D0: U13.N4(RGMII0_RXD0) ; off-sheet MII0_TX_D0
MII0_TX_D1: U13.N3(RGMII0_RXD1) ; off-sheet MII0_TX_D1
MII0_TX_D2: U13.N1(RGMII0_RXD3) ; off-sheet MII0_TX_D2
MII0_TX_D3: U13.P2(RGMII0_RXCTL) ; off-sheet MII0_TX_D3
MII0_TX_EN: U13.P1(RGMII0_RXD2) ; off-sheet MII0_TX_EN
RSTOUTn: R127.2 U13.E20(RSTOUTN) U16.3(~{RESET}/RFU) ; off-sheet RSTOUTn
RX_CLK_1: U13.E11(VIN2A_D18) ; off-sheet RX_CLK_1
RX_CTRL_1: U13.F11(VIN2A_D19) ; off-sheet RX_CTRL_1
RX_D0_1: U13.D13(VIN2A_D23) ; off-sheet RX_D0_1
RX_D1_1: U13.C13(VIN2A_D22) ; off-sheet RX_D1_1
RX_D2_1: U13.E13(VIN2A_D21) ; off-sheet RX_D2_1
RX_D3_1: U13.B13(VIN2A_D20) ; off-sheet RX_D3_1
SPIMEM_CLK: R38.2 R39.2 R40.1
SPIMEM_CSn: R124.2 U13.G4(GPMC_CS2) U16.7(~{CS})
SPIMEM_D0: U13.K5(GPMC_A16) U16.15(SI/IO0)
SPIMEM_D1: U13.G2(GPMC_A17) U16.8(SO/IO1)
SPIMEM_D2: R33.1 U13.K6(GPMC_A15) U16.9(~{WP}/IO2)
SPIMEM_D3: R32.1 U13.H4(GPMC_A14) U16.1(~{HOLD}/IO3)
SPIMEM_RTCLK: R39.1 U13.H3(GPMC_A13)
SW_3V3: C7.1 R31.2 R32.2 R33.2 R44.2 R46.2 R48.2 R99.1 R101.2 R102.2 R109.2 R113.2 R115.2 R116.2 R120.2 R124.1 R128.1 R131.2 R132.2 U12.6(VDDOUT) U12.7(VDDOUT) U16.2(VCC) U16.14(VIO/RFU) ; off-sheet SW_3V3
SYS_CLK1: R30.2 R98.2 U13.Y12(XI_OSC0) ; off-sheet SYS_CLK1
SYSBOOT0: R100.2 U13.F1(GPMC_AD0) ; off-sheet SYSBOOT0
SYSBOOT1: R104.2 U13.E2(GPMC_AD1) ; off-sheet SYSBOOT1
SYSBOOT2: R108.2 U13.E1(GPMC_AD2) ; off-sheet SYSBOOT2
SYSBOOT3: R112.2 U13.C1(GPMC_AD3) ; off-sheet SYSBOOT3
SYSBOOT4: R118.2 U13.D1(GPMC_AD4) ; off-sheet SYSBOOT4
SYSBOOT5: R122.2 U13.D2(GPMC_AD5) ; off-sheet SYSBOOT5
SYSBOOT6: R126.2 U13.B1(GPMC_AD6) ; off-sheet SYSBOOT6
SYSBOOT7: R129.2 U13.B2(GPMC_AD7) ; off-sheet SYSBOOT7
SYSBOOT8: R99.2 U13.C2(GPMC_AD8) ; off-sheet SYSBOOT8
SYSBOOT9: R103.2 U13.D3(GPMC_AD9) ; off-sheet SYSBOOT9
SYSBOOT10: R107.2 U13.A2(GPMC_AD10) ; off-sheet SYSBOOT10
SYSBOOT11: R111.2 U13.B3(GPMC_AD11) ; off-sheet SYSBOOT11
SYSBOOT12: R117.2 U13.C3(GPMC_AD12) ; off-sheet SYSBOOT12
SYSBOOT13: R121.2 U13.C4(GPMC_AD13) ; off-sheet SYSBOOT13
SYSBOOT14: R125.2 U13.A3(GPMC_AD14) ; off-sheet SYSBOOT14
SYSBOOT15: R128.2 U13.B4(GPMC_AD15) ; off-sheet SYSBOOT15
TX_CLK_1: U13.B11(VIN2A_D12) ; off-sheet TX_CLK_1
TX_CTRL_1: U13.D11(VIN2A_D13) ; off-sheet TX_CTRL_1
TX_D0_1: U13.A13(VIN2A_D17) ; off-sheet TX_D0_1
TX_D1_1: U13.A12(VIN2A_D16) ; off-sheet TX_D1_1
TX_D2_1: U13.B12(VIN2A_D15) ; off-sheet TX_D2_1
TX_D3_1: U13.C11(VIN2A_D14) ; off-sheet TX_D3_1
NetC194_1: C194.1 U12.14(XOUT) Y1.1(OSC1)
NetC222_1: C222.1 U12.1(XIN/CLK) Y1.2(OSC2)
NetC231_1: C231.1 R114.2 R116.1 U13.K24(RESETN)
NetR1_1: R1.1 U12.11(Y1)
NetR19_1: R19.1 U12.9(Y2)
NetR30_1: R30.1 U12.8(Y3)
NetR31_1: R31.1 SDA_CLK.1 U12.13(SDA/S1)
NetR38_1: R38.1 U16.16(SCK)
NetR40_2: R40.2 U13.F2(GPMC_A18)
NetR43_1: R43.1 R44.1 R100.1
NetR45_1: R45.1 R46.1 R104.1
NetR47_1: R47.1 R101.1 R108.1
NetR48_1: R48.1 SCL_CLK.1 U12.12(SCL/S2)
NetR102_1: R102.1 R105.1 R112.1
NetR106_1: R106.1 R109.1 R118.1
NetR110_1: R110.1 R113.1 R122.1
NetR115_1: R115.1 R119.1 R126.1
NetR120_1: R120.1 R123.1 R129.1
NetR133_1: R133.1 U13.E14(EMU2)
NetR134_1: R134.1 U13.K25(RTCK)
NetR135_1: R135.1 U13.J20(TDO)

Not connected (* = marked no-connect by the designer): U12 2(S0)* 4(VCTRL)*; U13 A4(GPMC_A19)* A5(GPMC_A26)* A6(GPMC_CS1) A14(MCASP1_AXR5)* A15(MCASP1_AXR4)* A16(MCASP1_AXR7)* A17(MCASP1_AXR6)* A18(MCASP1_AXR8)* A19(MCASP1_AXR12)* A20(MCASP2_AXR0)* A21(MCASP2_AXR2)* A22(MCASP3_ACLKX)* A23(MCASP3_FSX)* A24(MCASP4_AXR0)* AA1(MMC3_DAT5)* AA2(MMC3_DAT1)* AA3(MMC3_DAT2)* AA4(MMC3_DAT6)* AA5(MCASP5_AXR0)* AA6(USB2_DRVVBUS)* AA11(XO_OSC1)* AB1(MMC3_DAT7)* AB2(CSI2_0_DY0)* AB6(USB2_DP)* AB7(USB1_DM)* AB9(LJCB_CLKN)* AB12(XO_OSC0)* AC1(CSI2_0_DX0)* AC2(CSI2_0_DY1)* AC3(MCASP5_ACLKX)* AC4(MCASP5_AXR1)* AC5(USB2_DM)* AC6(USB1_DP)* AC8(LJCB_CLKP)* AC10(WAKEUP0)* AD1(CSI2_0_DX1)* AD2(CSI2_0_DY2)* AD3(USB1_DRVVBUS)* AD4(USB_TXP0)* AD6(USB_RXP0)* AD7(PCIE_RXP0)* AD9(PCIE_TXP0)* AD10(HDMI1_CLOCKY)* AD12(HDMI1_DATA0Y)* AD13(HDMI1_DATA1Y)* AD15(HDMI1_DATA2Y)* AE2(CSI2_0_DX2)* AE3(USB_TXN0)* AE5(USB_RXN0)* AE6(PCIE_RXN0)* AE8(PCIE_TXN0)* AE9(HDMI1_CLOCKX)* AE11(HDMI1_DATA0X)* AE12(HDMI1_DATA1X)* AE14(HDMI1_DATA2X)* B5(GPMC_A23)* B6(GPMC_A27)* B14(MCASP1_AXR1)* B15(MCASP1_AXR3)* B16(MCASP1_AXR10)* B17(MCASP1_AXR9)* B18(MCASP1_AXR11)* B19(MCASP2_AXR1)* B20(MCASP2_AXR4)* B21(MCASP2_AXR3)* B22(MCASP3_AXR0)* B23(MCASP3_AXR1)* B24(SPI1_CS0)* B25(MCASP4_FSX)* C5(GPMC_A22)* C6(GPMC_A25)* C14(MCASP1_AXR2)* C16(MCASP1_ACLKX)* C17(MCASP1_FSX)* C19(MCASP2_AXR5)* C20(MCASP2_AXR7)* C23(MCASP4_ACLKX)* C24(SPI1_SCLK)* C25(SPI1_CS1)* D6(GPMC_A21)* D7(GPMC_A24)* D14(MCASP1_AXR0)* D16(MCASP1_ACLKR)* D17(MCASP1_FSR)* D19(MCASP2_FSX)* D20(MCASP2_AXR6)* D23(MCASP4_AXR1)* D24(SPI1_D1)* D25(SPI1_D0)* E7(GPMC_A20)* E16(MCASP1_AXR14)* E17(MCASP1_AXR13)* E19(MCASP2_ACLKX)* E24(SPI1_CS2)* E25(SPI1_CS3)* F3(GPMC_CS0)* F6(GPMC_WAIT0)* F16(MCASP1_AXR15)* F20(RSV)* F23(I2C2_SDA)* F24(SPI2_CS0)* F25(SPI2_D1)* G1(GPMC_A12)* G3(GPMC_CS3)* G20(RSV)* G21(I2C2_SCL)* G24(SPI2_D0)* G25(SPI2_SCLK)* H1(GPMC_A9)* H2(GPMC_BEN0)* H6(GPMC_BEN1)* H24(XREF_CLK2)* H25(XREF_CLK3)* J1(GPMC_A6)* J2(GPMC_A10)* J24(XREF_CLK1)* J25(XREF_CLK0)* K1(GPMC_A7)* K2(GPMC_A5)* K3(GPMC_A4)* K4(GPMC_A8)* K20(RSV)* L1(GPMC_A3)* L2(GPMC_A2)* L3(GPMC_A11)* L6(MDIO_D)* L19(RSV)* L20(UART1_CTSN)* L24(NMIN_DSP)* L25(UART1_RXD)* M1(GPMC_A0)* M2(GPMC_A1)* M24(UART1_RTSN)* M25(UART1_TXD)* N22(UART2_CTSN)* N23(UART2_RXD)* N24(UART2_RTSN)* N25(UART2_TXD)* P5(RMII_MHZ_50_CLK)* T1(MLBP_DAT_N)* T2(MLBP_DAT_P)* T3(MLBP_SIG_P)* U1(MLBP_CLK_N)* U2(MLBP_CLK_P)* U3(MMC1_CLK)* U4(MLBP_SIG_N)* U5(MMC1_SDCD)* U6(MCASP5_FSX)* V1(MMC1_DAT3)* V2(MMC1_DAT1)* V3(MMC1_DAT0)* V4(MMC1_CMD)* V5(MMC1_SDWP)* W1(MMC1_DAT2)* W2(MMC3_DAT3)* Y1(MMC3_CMD)* Y2(MMC3_CLK)* Y3(MMC3_DAT4)* Y4(MMC3_DAT0)* Y5(GPIO6_10)*; U16 4(DNU)* 5(DNU)* 6(RFU)* 11(DNU)* 12(DNU)* 13(NC)*

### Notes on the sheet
- SYSBOOT[15:0] = 10XX XX01 0011 0111
- SYS_CLK1 = 20MHz
- ROUTE THE FOLLOWING SIGNALS AS A GROUP
  WITH A NET LENGTH LESS THEN 2.75
  INCHES AND 60ps OF SKEW. PLACE THE
  DUAL RESISTOR CLOSE TOGETHER NEAR THE
  PIN OF THE FLASH.
  AQSPI1_SCLK
  AQSPI1_RTCLK
  AQSPI1_CS[0]
  AQSPI1_D[0]
  AQSPI1_D[1]
  AQSPI1_D[2]
  AQSPI1_D[3]
- (near R43) Booting device: QSPI (boot part)

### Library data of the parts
C7 = 0402ZC103KAT2A: CAP, CERM, 0.01 µF, 10 V, +/- 10%, X7R, 0402; Manufacturer: AVX; Polarized: N; CompType: Capacitor; Value: 0.01uF; U/M: EA; Cap_F: 0.00000001; Tolerance_%: 10; Value1: Unknown; Value2: 10V; TaMin_C: -55; TaMax_C: 125; Cap_Case: 0402; SizeArea_mm2: 0.5; SizeAreaWB_mm2: 3; SizeX_mm: 1; SizeZ_mm: 0.6; AEC Category: Q200
C194 C222 = GRM1885C1H130JA01D: CAP, CERM, 13 pF, 50 V, +/- 5%, C0G/NP0, 0603; Manufacturer: MuRata; Polarized: N; CompType: Capacitor; Value: 13pF; U/M: EA; Cap_F: 0.000000000013; Tolerance_%: 5; Value1: Unknown; VDC_V: 50; Value2: 50V; TaMin_C: -55; TaMax_C: 125; SizeArea_mm2: 1.28; SizeAreaWB_mm2: 4.68; SizeX_mm: 1.6; SizeY_mm: 0.8; SizeZ_mm: 1; AEC Category: Q200
C231 = CGA1A2X7R1E102K030BA: CAP, CERM, 1000 pF, 25 V, +/- 10%, X7R, AEC-Q200 Grade 1, 0201; Manufacturer: TDK; Polarized: N; CompType: Capacitor; Value: 1000pF; U/M: EA; Cap_F: 0.000000001; Tolerance_%: 10; ESR_ohm: 2.5722; Value1: 2.5722 ohm; VDC_V: 25; Value2: 25V; IRMS_A: 0.143158; TaMin_C: -55; TaMax_C: 125; SizeArea_mm2: 0.18; SizeAreaWB_mm2: 2.08; SizeX_mm: 0.6; SizeY_mm: 0.3; SizeZ_mm: 0.33; AEC Category: Q200; AEC Qualified: Y; AEC Grade: 1
R1 R19 = RC0603FR-0733RL: RES, 33.0, 1%, 0.1 W, 0603; Manufacturer: Yageo America; CompType: Resistor; Value: 33.0; Res_ohm: 33; Value_Code: 33R0; Tolerance_%: 1; Power_W: 0.1; Value2: 0.1W; VDC_V: 150; TempCo: 200 ppm/C; SizeArea_mm2: 1.28; SizeX_mm: 1.6; SizeY_mm: 0.8; U/M: EA; AEC Category: Q200
R30 = RC0603FR-0768RL: RES, 68.0, 1%, 0.1 W, 0603; Manufacturer: Yageo America; CompType: Resistor; Value: 68.0; Res_ohm: 68; Value_Code: 68R0; Tolerance_%: 1; Power_W: 0.1; Value2: 0.1W; VDC_V: 150; TempCo: 200 ppm/C; SizeArea_mm2: 1.28; SizeX_mm: 1.6; SizeY_mm: 0.8; U/M: EA; AEC Category: Q200
R31 R48 R131 R132 = RC0201FR-074K99L: RES, 4.99 k, 1%, 0.05 W, 0201; Manufacturer: Yageo America; CompType: Resistor; Value: 4.99k; Res_ohm: 4990; Value_Code: 4k99; Tolerance_%: 1; Power_W: 0.05; Value2: 0.05W; VDC_V: 25; TempCo: 200 ppm/C; SizeArea_mm2: 0.18; SizeX_mm: 0.6; SizeY_mm: 0.3; SizeZ_mm: 0.26; EIA_Code: E96; U/M: EA; AEC Category: Q200; AEC Qualified: N
R32 R33 R124 = RCG060310K0FKEA: RES, 10.0 k, 1%, 0.1 W, 0603; Manufacturer: Vishay Draloric; CompType: Resistor; Value: 10.0k; Res_ohm: 10000; Value_Code: 10k0; Tolerance_%: 1; Power_W: 0.1; Value2: 0.1W; VDC_V: 75; TempCo: 100 ppm/C; SizeArea_mm2: 1.28; SizeX_mm: 1.6; SizeY_mm: 0.8; EIA_Code: E96; U/M: EA; AEC Category: Q200; AEC Qualified: N
R38 R39 = CRCW060310R0FKEA: RES, 10.0, 1%, 0.1 W, 0603; Manufacturer: Vishay-Dale; CompType: Resistor; Value: 10.0; Res_ohm: 10; Value_Code: 10R0; Tolerance_%: 1; Power_W: 0.1; Value2: 0.1W; VDC_V: 75; TempCo: 100 ppm/C; SizeArea_mm2: 1.28; SizeX_mm: 1.6; SizeY_mm: 0.8; EIA_Code: E96; U/M: EA; AEC Category: Q200
R40 = ERJ-3GEY0R00V: RES, 0, 5%, 0.1 W, 0603; Manufacturer: Panasonic; CompType: Resistor; Value: 0; Value_Code: 0000; Tolerance_%: 5; Power_W: 0.1; Value2: 0.1W; VDC_V: 50; TempCo: 600 ppm/C; SizeArea_mm2: 1.28; SizeX_mm: 1.6; SizeY_mm: 0.8; SizeZ_mm: 1; EIA_Code: E24; U/M: EA; AEC Category: Q200
R43-R47 R101 R102 R105 R106 R109 R110 R113 R115 R119 R120 R123 = RMCF0603ZT0R00: RES, 0, 1%, 0.1 W, AEC-Q200 Grade 0, 0603; Manufacturer: Stackpole Electronics Inc; CompType: Resistor; Value: 0; Tolerance_%: 1; Power_W: 0.1; Value2: 0.1W; TempCo: ppm/C; SizeArea_mm2: 1.28; SizeX_mm: 1.6; SizeY_mm: 0.8; U/M: EA; AEC Category: Q200; AEC Qualified: Y
R98 = CRCW060391R0JNEA: RES, 91, 5%, 0.1 W, 0603; Manufacturer: Vishay-Dale; CompType: Resistor; Value: 91; Value_Code: 91R0; Tolerance_%: 5; Power_W: 0.1; Value2: 0.1W; VDC_V: 75; TempCo: 200 ppm/C; SizeArea_mm2: 1.28; SizeX_mm: 1.6; SizeY_mm: 0.8; SizeZ_mm: 1; EIA_Code: E24; U/M: EA; AEC Category: Q200
R99 R100 R103 R104 R107 R108 R111 R112 R116-R118 R121 R122 R125 R126 R128 R129 = CRCW020110K0FKED: RES, 10.0 k, 1%, 0.05 W, 0201; Manufacturer: Vishay-Dale; CompType: Resistor; Value: 10.0k; Res_ohm: 10000; Value_Code: 10k0; Tolerance_%: 1; Power_W: 0.05; Value2: 0.05W; VDC_V: 30; TempCo: 100 ppm/C; SizeArea_mm2: 0.18; SizeX_mm: 0.6; SizeY_mm: 0.3; SizeZ_mm: 0.26; EIA_Code: E96; U/M: EA; AEC Category: Q200; AEC Qualified: N
R114 = RC0201FR-07100RL: RES, 100, 1%, 0.05 W, 0201; Manufacturer: Yageo America; CompType: Resistor; Value: 100; Value_Code: 100R; Tolerance_%: 1; Power_W: 0.05; Value2: 0.05W; VDC_V: 25; TempCo: 200 ppm/C; SizeArea_mm2: 0.18; SizeX_mm: 0.6; SizeY_mm: 0.3; SizeZ_mm: 0.26; EIA_Code: E96; U/M: EA; AEC Category: Q200; AEC Qualified: N
R127 = RC0201JR-072K2L: RES, 2.2 k, 5%, 0.05 W, 0201; Manufacturer: Yageo America; CompType: Resistor; Value: 2.2k; Res_ohm: 2200; Value_Code: 2k20; Tolerance_%: 5; Power_W: 0.05; Value2: 0.05W; VDC_V: 25; TempCo: 200 ppm/C; SizeArea_mm2: 0.18; SizeX_mm: 0.6; SizeY_mm: 0.3; SizeZ_mm: 0.26; EIA_Code: E24; U/M: EA; AEC Category: Q200; AEC Qualified: N
R133-R135 = CRCW040222R0JNED: RES, 22, 5%, 0.063 W, 0402; Manufacturer: Vishay-Dale; CompType: Resistor; Value: 22; Value_Code: 22R0; Tolerance_%: 5; Power_W: 0.063; Value2: 0.063W; VDC_V: 50; TempCo: 200 ppm/C; SizeArea_mm2: 0.5; SizeX_mm: 1; SizeZ_mm: 0.6; EIA_Code: E24; U/M: EA; AEC Category: Q200
SCL_CLK SDA_CLK = PAD_3.2x1.9MM_SMD: 3.2x1.9mm Pad, SMD; Manufacturer: Any
U12 = CDCE913QPWRQ1: Programmable 1-PLL VCXO Clock Synthesizer with 2.5-V or 3.3-V LVCMOS Outputs, PW0014A (TSSOP-14); Manufacturer: Texas Instruments; SymbolCreator: a0411947; SizeArea_mm2: 32; SizeAreaWB_mm2: 58.8; SizeX_mm: 6.4; SizeY_mm: 5; SizeZ_mm: 1.2; CompType: IC; U/M: EA
U13 = DRA710CBD: as U13 on sheet DIG PWR
U16 = S25FL256SAGMFB010: 256 Mbit (32 Mbyte) 3.0V SPI Flash Memory; Manufacturer: Cypress Semiconductor; SymbolCreator: Altium
Y1 = NX5032GA-25.000M-STD-CSK-4: Crystal, 25MHz,  SMD; Manufacturer: NDK; SymbolCreator: a0412235; U/M: EA; TaMin_C: -40; TaMax_C: 150; Frequency Stability: ±30ppm

## Sheet J6E DDR.SchDoc: J6E DDR
size 431 x 279 mm; Date: Not shown in title block; ApprovedBy: Not shown in title block; CheckedBy: Not shown in title block; Author: Not shown in title block; CompanyName: Not shown in title block; DrawnBy: Donovan Porter; Engineer: Not shown in title block; Organization: Not shown in title block; Address1: Not shown in title block; Address2: Not shown in title block; Address3: Not shown in title block; Address4: Not shown in title block; DocumentNumber: 3; Revision: Use project parameter SCH_Rev; SheetNumber: 3; SheetTotal: 12; PageSetup: Record=PageOptions¦CenterHorizontal=True¦CenterVertical=True¦PrintScale=1.00¦XCorrection=1.00¦YCorrection=1.00¦PrintKind=0¦BorderSize=5000000¦LeftOffset=0¦BottomOffset=0¦Orientation=2¦PaperLength=1000¦PaperWidth=1000¦Scale=100¦PaperSource=15¦PrintQuality=600¦MediaType=1¦DitherType=10¦PaperKind=Letter¦PrintScaleMode=1
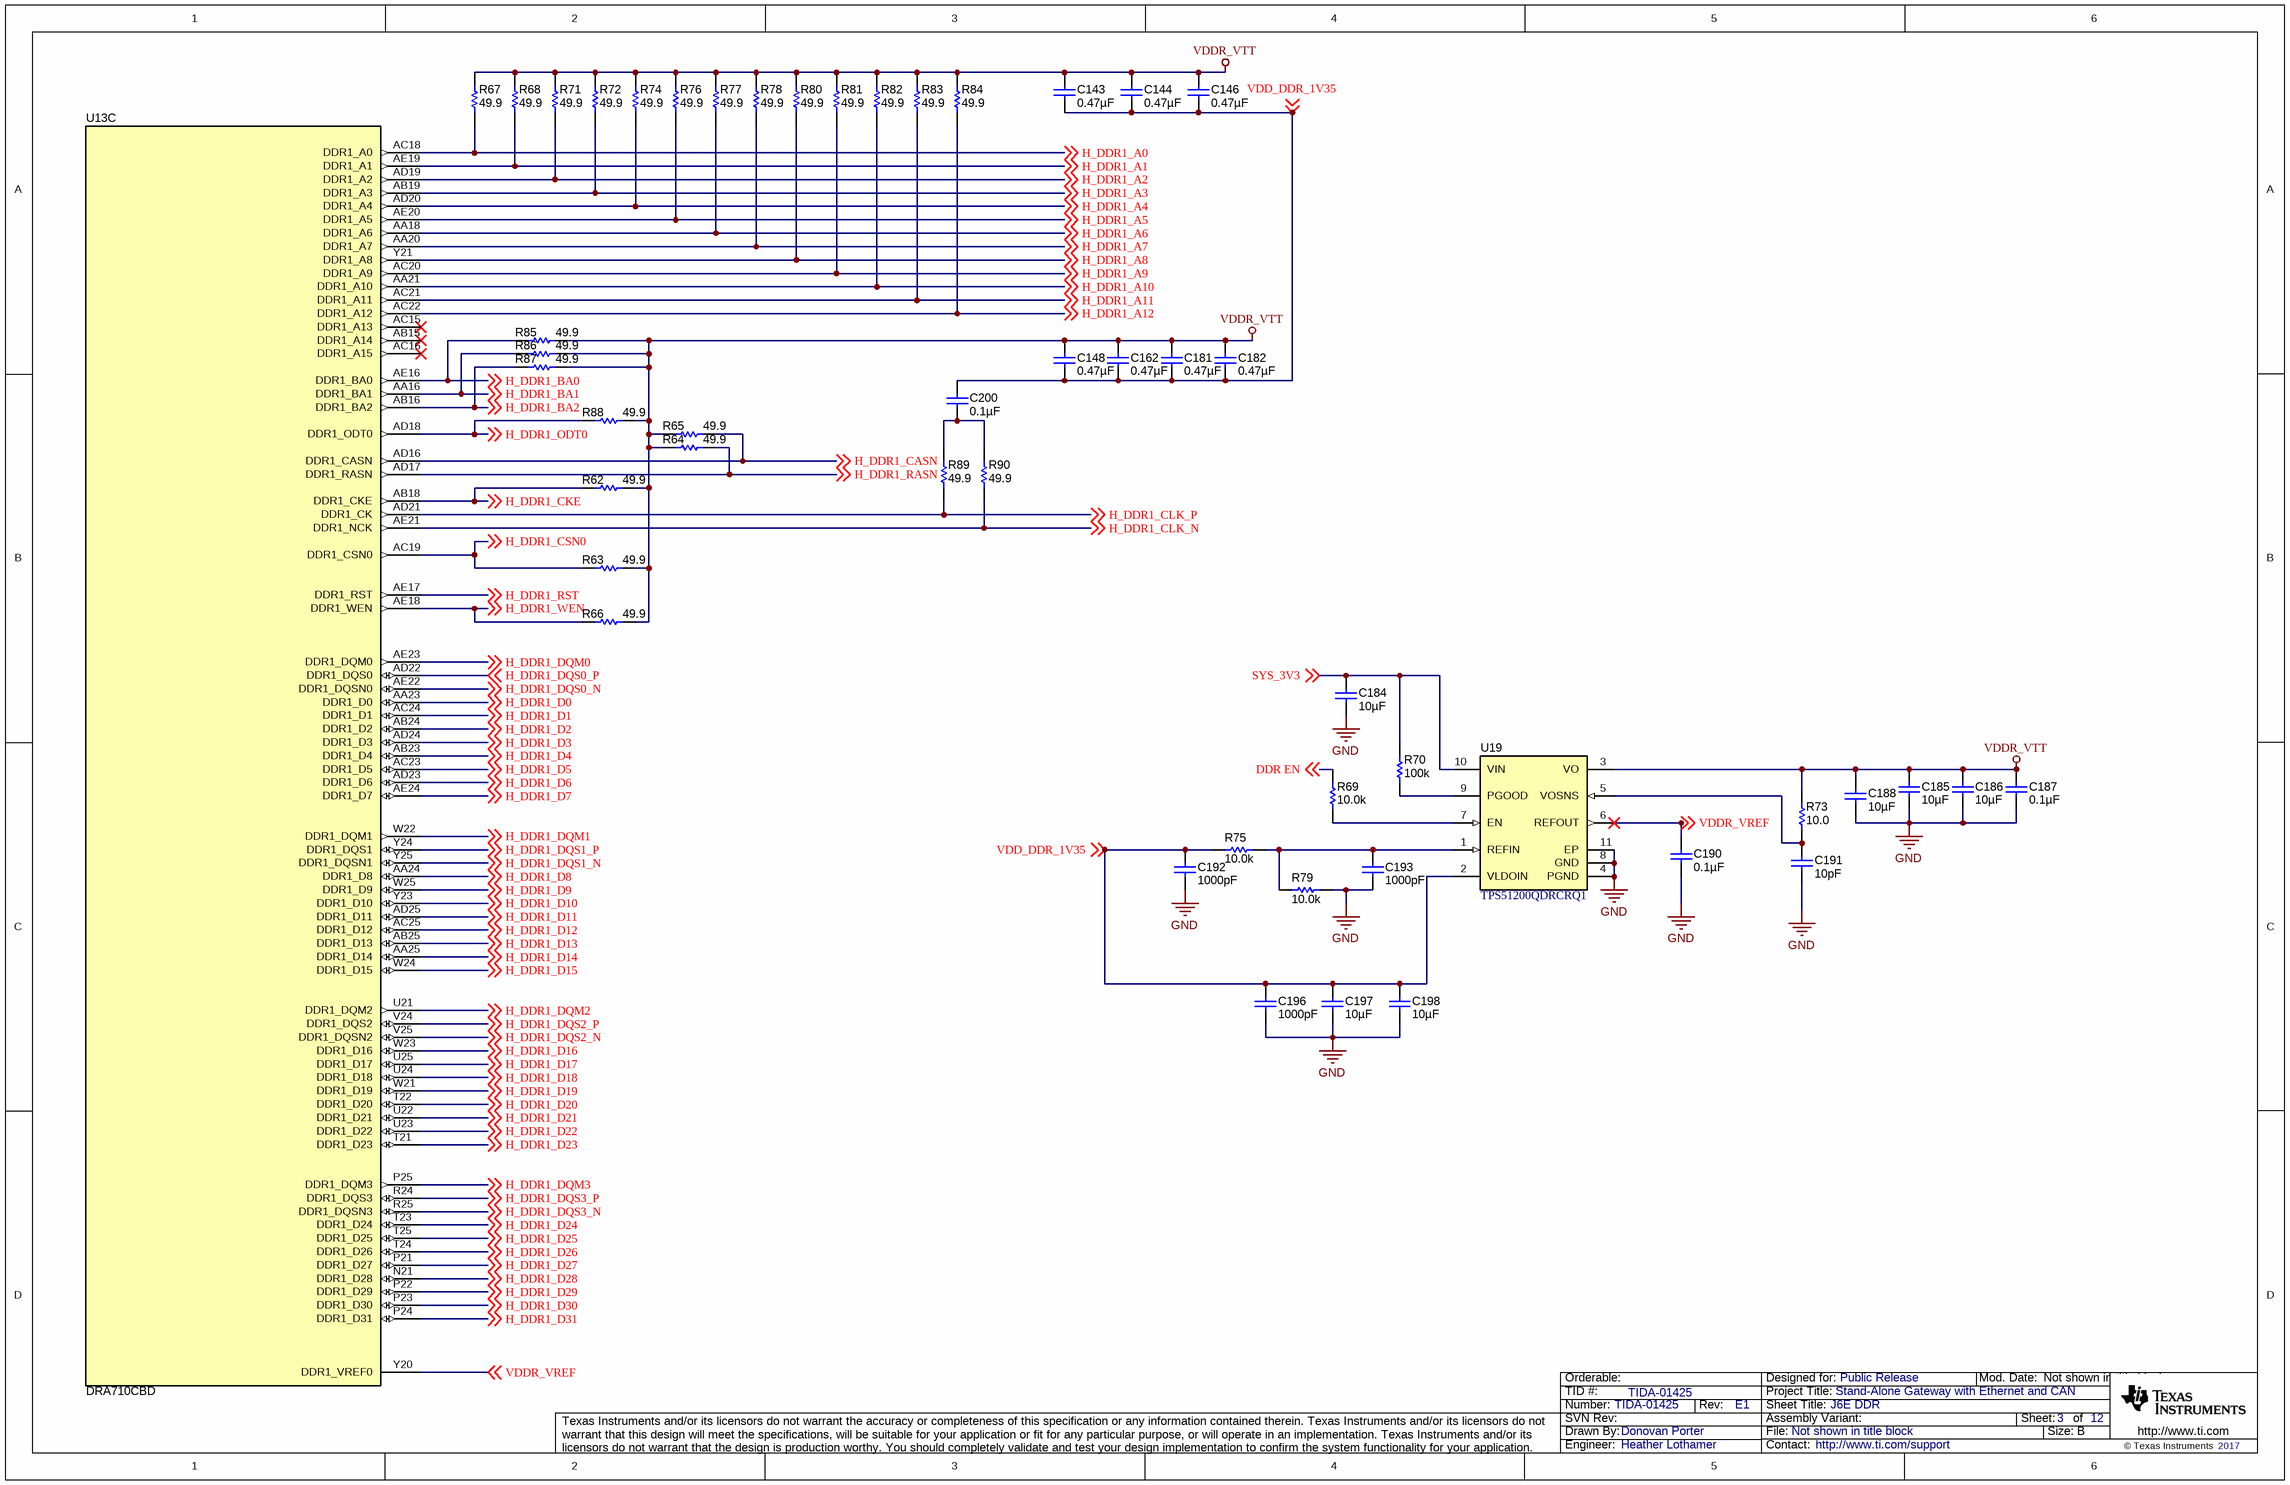
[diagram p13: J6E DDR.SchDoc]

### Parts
C143  ValueDisplayed: 0.47µF  [0402L]  (hidden comment: GCM155C71A474KE36D)
C144  ValueDisplayed: 0.47µF  [0402L]  (hidden comment: GCM155C71A474KE36D)
C146  ValueDisplayed: 0.47µF  [0402L]  (hidden comment: GCM155C71A474KE36D)
C148  ValueDisplayed: 0.47µF  [0402L]  (hidden comment: GCM155C71A474KE36D)
C162  ValueDisplayed: 0.47µF  [0402L]  (hidden comment: GCM155C71A474KE36D)
C181  ValueDisplayed: 0.47µF  [0402L]  (hidden comment: GCM155C71A474KE36D)
C182  ValueDisplayed: 0.47µF  [0402L]  (hidden comment: GCM155C71A474KE36D)
C184  ValueDisplayed: 10µF  [1206_190L]  (hidden comment: CGA5L1X7R1C106K160AC)
C185  ValueDisplayed: 10µF  [1206_190L]  (hidden comment: CGA5L1X7R1C106K160AC)
C186  ValueDisplayed: 10µF  [1206_190L]  (hidden comment: CGA5L1X7R1C106K160AC)
C187  ValueDisplayed: 0.1µF  [0402L]  (hidden comment: C0402C104K4RACAUTO)
C188  ValueDisplayed: 10µF  [1206_190L]  (hidden comment: CGA5L1X7R1C106K160AC)
C190  ValueDisplayed: 0.1µF  [0402L]  (hidden comment: C0402C104K4RACAUTO)
C191  ValueDisplayed: 10pF  [0603L]  (hidden comment: CGA3E2C0G1H100D080AA)
C192  ValueDisplayed: 1000pF  [0201_033]  (hidden comment: CGA1A2X7R1E102K030BA)
C193  ValueDisplayed: 1000pF  [0201_033]  (hidden comment: CGA1A2X7R1E102K030BA)
C196  ValueDisplayed: 1000pF  [0201_033]  (hidden comment: CGA1A2X7R1E102K030BA)
C197  ValueDisplayed: 10µF  [1206_190L]  (hidden comment: CGA5L1X7R1C106K160AC)
C198  ValueDisplayed: 10µF  [1206_190L]  (hidden comment: CGA5L1X7R1C106K160AC)
C200  ValueDisplayed: 0.1µF  [0402L]  (hidden comment: GCM155R71C104KA55D)
R62  ValueDisplayed: 49.9  [0402L]  (hidden comment: CRCW040249R9FKED)
R63  ValueDisplayed: 49.9  [0402L]  (hidden comment: CRCW040249R9FKED)
R64  ValueDisplayed: 49.9  [0402L]  (hidden comment: CRCW040249R9FKED)
R65  ValueDisplayed: 49.9  [0402L]  (hidden comment: CRCW040249R9FKED)
R66  ValueDisplayed: 49.9  [0402L]  (hidden comment: CRCW040249R9FKED)
R67  ValueDisplayed: 49.9  [0402L]  (hidden comment: CRCW040249R9FKED)
R68  ValueDisplayed: 49.9  [0402L]  (hidden comment: CRCW040249R9FKED)
R69  ValueDisplayed: 10.0k  [0603L]  (hidden comment: RCG060310K0FKEA)
R70  ValueDisplayed: 100k  [0603L]  (hidden comment: RC0603FR-07100KL)
R71  ValueDisplayed: 49.9  [0402L]  (hidden comment: CRCW040249R9FKED)
R72  ValueDisplayed: 49.9  [0402L]  (hidden comment: CRCW040249R9FKED)
R73  ValueDisplayed: 10.0  [0603L]  (hidden comment: CRCW060310R0FKEA)
R74  ValueDisplayed: 49.9  [0402L]  (hidden comment: CRCW040249R9FKED)
R75  ValueDisplayed: 10.0k  [0603L]  (hidden comment: CRCW060310K0FKEA)
R76  ValueDisplayed: 49.9  [0402L]  (hidden comment: CRCW040249R9FKED)
R77  ValueDisplayed: 49.9  [0402L]  (hidden comment: CRCW040249R9FKED)
R78  ValueDisplayed: 49.9  [0402L]  (hidden comment: CRCW040249R9FKED)
R79  ValueDisplayed: 10.0k  [0603L]  (hidden comment: CRCW060310K0FKEA)
R80  ValueDisplayed: 49.9  [0402L]  (hidden comment: CRCW040249R9FKED)
R81  ValueDisplayed: 49.9  [0402L]  (hidden comment: CRCW040249R9FKED)
R82  ValueDisplayed: 49.9  [0402L]  (hidden comment: CRCW040249R9FKED)
R83  ValueDisplayed: 49.9  [0402L]  (hidden comment: CRCW040249R9FKED)
R84  ValueDisplayed: 49.9  [0402L]  (hidden comment: CRCW040249R9FKED)
R85  ValueDisplayed: 49.9  [0402L]  (hidden comment: CRCW040249R9FKED)
R86  ValueDisplayed: 49.9  [0402L]  (hidden comment: CRCW040249R9FKED)
R87  ValueDisplayed: 49.9  [0402L]  (hidden comment: CRCW040249R9FKED)
R88  ValueDisplayed: 49.9  [0402L]  (hidden comment: CRCW040249R9FKED)
R89  ValueDisplayed: 49.9  [0402L]  (hidden comment: CRCW040249R9FKED)
R90  ValueDisplayed: 49.9  [0402L]  (hidden comment: CRCW040249R9FKED)
U13  DRA710CBD  [CBD0538A]  (part C of 5)
U19  TPS51200QDRCRQ1  [DRC0010J]

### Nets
GND: C184.2 C185.2 C186.2 C187.2 C188.2 C190.2 C191.2 C192.2 C193.2 C196.2 C197.2 C198.2 R79.2 U19.4(PGND) U19.8(GND) U19.11(EP)
VDDR_VTT: C143.1 C144.1 C146.1 C148.1 C162.1 C181.1 C182.1 C185.1 C186.1 C187.1 C188.1 R62.2 R63.2 R64.1 R65.1 R66.2 R67.2 R68.2 R71.2 R72.2 R73.2 R74.2 R76.2 R77.2 R78.2 R80.2 R81.2 R82.2 R83.2 R84.2 R85.2 R86.2 R87.2 R88.2 U19.3(VO)
DDR EN: R69.2 ; off-sheet DDR EN
H_DDR1_A0: R67.1 U13.AC18(DDR1_A0) ; off-sheet H_DDR1_A0
H_DDR1_A1: R68.1 U13.AE19(DDR1_A1) ; off-sheet H_DDR1_A1
H_DDR1_A2: R71.1 U13.AD19(DDR1_A2) ; off-sheet H_DDR1_A2
H_DDR1_A3: R72.1 U13.AB19(DDR1_A3) ; off-sheet H_DDR1_A3
H_DDR1_A4: R74.1 U13.AD20(DDR1_A4) ; off-sheet H_DDR1_A4
H_DDR1_A5: R76.1 U13.AE20(DDR1_A5) ; off-sheet H_DDR1_A5
H_DDR1_A6: R77.1 U13.AA18(DDR1_A6) ; off-sheet H_DDR1_A6
H_DDR1_A7: R78.1 U13.AA20(DDR1_A7) ; off-sheet H_DDR1_A7
H_DDR1_A8: R80.1 U13.Y21(DDR1_A8) ; off-sheet H_DDR1_A8
H_DDR1_A9: R81.1 U13.AC20(DDR1_A9) ; off-sheet H_DDR1_A9
H_DDR1_A10: R82.1 U13.AA21(DDR1_A10) ; off-sheet H_DDR1_A10
H_DDR1_A11: R83.1 U13.AC21(DDR1_A11) ; off-sheet H_DDR1_A11
H_DDR1_A12: R84.1 U13.AC22(DDR1_A12) ; off-sheet H_DDR1_A12
H_DDR1_BA0: R85.1 U13.AE16(DDR1_BA0) ; off-sheet H_DDR1_BA0
H_DDR1_BA1: R86.1 U13.AA16(DDR1_BA1) ; off-sheet H_DDR1_BA1
H_DDR1_BA2: R87.1 U13.AB16(DDR1_BA2) ; off-sheet H_DDR1_BA2
H_DDR1_CASN: R65.2 U13.AD16(DDR1_CASN) ; off-sheet H_DDR1_CASN
H_DDR1_CKE: R62.1 U13.AB18(DDR1_CKE) ; off-sheet H_DDR1_CKE
H_DDR1_CLK_N: R90.1 U13.AE21(DDR1_NCK) ; off-sheet H_DDR1_CLK_N
H_DDR1_CLK_P: R89.1 U13.AD21(DDR1_CK) ; off-sheet H_DDR1_CLK_P
H_DDR1_CSN0: R63.1 U13.AC19(DDR1_CSN0) ; off-sheet H_DDR1_CSN0
H_DDR1_D0: U13.AA23(DDR1_D0) ; off-sheet H_DDR1_D0
H_DDR1_D1: U13.AC24(DDR1_D1) ; off-sheet H_DDR1_D1
H_DDR1_D2: U13.AB24(DDR1_D2) ; off-sheet H_DDR1_D2
H_DDR1_D3: U13.AD24(DDR1_D3) ; off-sheet H_DDR1_D3
H_DDR1_D4: U13.AB23(DDR1_D4) ; off-sheet H_DDR1_D4
H_DDR1_D5: U13.AC23(DDR1_D5) ; off-sheet H_DDR1_D5
H_DDR1_D6: U13.AD23(DDR1_D6) ; off-sheet H_DDR1_D6
H_DDR1_D7: U13.AE24(DDR1_D7) ; off-sheet H_DDR1_D7
H_DDR1_D8: U13.AA24(DDR1_D8) ; off-sheet H_DDR1_D8
H_DDR1_D9: U13.W25(DDR1_D9) ; off-sheet H_DDR1_D9
H_DDR1_D10: U13.Y23(DDR1_D10) ; off-sheet H_DDR1_D10
H_DDR1_D11: U13.AD25(DDR1_D11) ; off-sheet H_DDR1_D11
H_DDR1_D12: U13.AC25(DDR1_D12) ; off-sheet H_DDR1_D12
H_DDR1_D13: U13.AB25(DDR1_D13) ; off-sheet H_DDR1_D13
H_DDR1_D14: U13.AA25(DDR1_D14) ; off-sheet H_DDR1_D14
H_DDR1_D15: U13.W24(DDR1_D15) ; off-sheet H_DDR1_D15
H_DDR1_D16: U13.W23(DDR1_D16) ; off-sheet H_DDR1_D16
H_DDR1_D17: U13.U25(DDR1_D17) ; off-sheet H_DDR1_D17
H_DDR1_D18: U13.U24(DDR1_D18) ; off-sheet H_DDR1_D18
H_DDR1_D19: U13.W21(DDR1_D19) ; off-sheet H_DDR1_D19
H_DDR1_D20: U13.T22(DDR1_D20) ; off-sheet H_DDR1_D20
H_DDR1_D21: U13.U22(DDR1_D21) ; off-sheet H_DDR1_D21
H_DDR1_D22: U13.U23(DDR1_D22) ; off-sheet H_DDR1_D22
H_DDR1_D23: U13.T21(DDR1_D23) ; off-sheet H_DDR1_D23
H_DDR1_D24: U13.T23(DDR1_D24) ; off-sheet H_DDR1_D24
H_DDR1_D25: U13.T25(DDR1_D25) ; off-sheet H_DDR1_D25
H_DDR1_D26: U13.T24(DDR1_D26) ; off-sheet H_DDR1_D26
H_DDR1_D27: U13.P21(DDR1_D27) ; off-sheet H_DDR1_D27
H_DDR1_D28: U13.N21(DDR1_D28) ; off-sheet H_DDR1_D28
H_DDR1_D29: U13.P22(DDR1_D29) ; off-sheet H_DDR1_D29
H_DDR1_D30: U13.P23(DDR1_D30) ; off-sheet H_DDR1_D30
H_DDR1_D31: U13.P24(DDR1_D31) ; off-sheet H_DDR1_D31
H_DDR1_DQM0: U13.AE23(DDR1_DQM0) ; off-sheet H_DDR1_DQM0
H_DDR1_DQM1: U13.W22(DDR1_DQM1) ; off-sheet H_DDR1_DQM1
H_DDR1_DQM2: U13.U21(DDR1_DQM2) ; off-sheet H_DDR1_DQM2
H_DDR1_DQM3: U13.P25(DDR1_DQM3) ; off-sheet H_DDR1_DQM3
H_DDR1_DQS0_N: U13.AE22(DDR1_DQSN0) ; off-sheet H_DDR1_DQS0_N
H_DDR1_DQS0_P: U13.AD22(DDR1_DQS0) ; off-sheet H_DDR1_DQS0_P
H_DDR1_DQS1_N: U13.Y25(DDR1_DQSN1) ; off-sheet H_DDR1_DQS1_N
H_DDR1_DQS1_P: U13.Y24(DDR1_DQS1) ; off-sheet H_DDR1_DQS1_P
H_DDR1_DQS2_N: U13.V25(DDR1_DQSN2) ; off-sheet H_DDR1_DQS2_N
H_DDR1_DQS2_P: U13.V24(DDR1_DQS2) ; off-sheet H_DDR1_DQS2_P
H_DDR1_DQS3_N: U13.R25(DDR1_DQSN3) ; off-sheet H_DDR1_DQS3_N
H_DDR1_DQS3_P: U13.R24(DDR1_DQS3) ; off-sheet H_DDR1_DQS3_P
H_DDR1_ODT0: R88.1 U13.AD18(DDR1_ODT0) ; off-sheet H_DDR1_ODT0
H_DDR1_RASN: R64.2 U13.AD17(DDR1_RASN) ; off-sheet H_DDR1_RASN
H_DDR1_RST: U13.AE17(DDR1_RST) ; off-sheet H_DDR1_RST
H_DDR1_WEN: R66.1 U13.AE18(DDR1_WEN) ; off-sheet H_DDR1_WEN
SYS_3V3: C184.1 R70.2 U19.10(VIN) ; off-sheet SYS_3V3
VDD_DDR_1V35: C143.2 C144.2 C146.2 C148.2 C162.2 C181.2 C182.2 C192.1 C196.1 C197.1 C198.1 C200.1 R75.1 U19.2(VLDOIN) ; off-sheet VDD_DDR_1V35
VDDR_VREF: C190.1 U13.Y20(DDR1_VREF0) U19.6(REFOUT) ; off-sheet VDDR_VREF
NetC191_1: C191.1 R73.1 U19.5(VOSNS)
NetC193_1: C193.1 R75.2 R79.1 U19.1(REFIN)
NetC200_2: C200.2 R89.2 R90.2
NetR69_1: R69.1 U19.7(EN)
NetR70_1: R70.1 U19.9(PGOOD)

Not connected (* = marked no-connect by the designer): U13 AB15(DDR1_A14)* AC15(DDR1_A13)* AC16(DDR1_A15)*

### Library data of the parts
C143 C144 C146 C148 C162 C181 C182 = GCM155C71A474KE36D: as C94-C97 on sheet DIG PWR
C184-C186 C188 C197 C198 = CGA5L1X7R1C106K160AC: CAP, CERM, 10 µF, 16 V, +/- 10%, X7R, AEC-Q200 Grade 1, 1206_190; Manufacturer: TDK; Polarized: N; CompType: Capacitor; Value: 10uF; U/M: EA; Cap_F: 0.00001; Tolerance_%: 10; Value1: Unknown; VDC_V: 16; Value2: 16V; TaMin_C: -55; TaMax_C: 125; Cap_Case: 1206; SizeArea_mm2: 5.12; SizeAreaWB_mm2: 10.92; SizeX_mm: 3.2; SizeY_mm: 1.6; SizeZ_mm: 1.9; AEC Category: Q200; AEC Qualified: Y; AEC Grade: 1
C187 C190 = C0402C104K4RACAUTO: CAP, CERM, 0.1 µF, 16 V, +/- 10%, X7R, AEC-Q200 Grade 1, 0402; Manufacturer: Kemet; Polarized: N; CompType: Capacitor; Value: 0.47uF; U/M: EA; Cap_F: 0.0000001; Tolerance_%: 10; Value1: Unknown; VDC_V: 16; Value2: 16V; TaMin_C: -55; TaMax_C: 125; Cap_Case: 0402; SizeArea_mm2: 0.5; SizeAreaWB_mm2: 3; SizeX_mm: 1; SizeZ_mm: 0.6; AEC Category: Q200; AEC Qualified: Y
C191 = CGA3E2C0G1H100D080AA: CAP, CERM, 10 pF, 50 V, +/- 5%, C0G/NP0, AEC-Q200 Grade 1, 0603; Manufacturer: TDK; Polarized: N; CompType: Capacitor; Value: 10pF; U/M: EA; Cap_F: 0.00000000001; Tolerance_%: 5; Value1: Unknown; VDC_V: 50; Value2: 50V; TaMin_C: -55; TaMax_C: 125; Cap_Case: 0603; SizeArea_mm2: 1.28; SizeAreaWB_mm2: 4.68; SizeX_mm: 1.6; SizeY_mm: 0.8; SizeZ_mm: 1; AEC Category: Q200; AEC Qualified: Y
C192 C193 C196 = CGA1A2X7R1E102K030BA: as C231 on sheet J6Entry
C200 = GCM155R71C104KA55D: CAP, CERM, 0.1 µF, 16 V, +/- 10%, X7R, 0402; Manufacturer: MuRata; Polarized: N; CompType: Capacitor; Value: 0.1uF; U/M: EA; Cap_F: 0.0000001; Tolerance_%: 10; Value1: Unknown; VDC_V: 16; Value2: 16V; TaMin_C: -55; TaMax_C: 125; Cap_Case: 0402; SizeArea_mm2: 0.5; SizeAreaWB_mm2: 3; SizeX_mm: 1; SizeZ_mm: 0.6; AEC Category: Q200
R62-R68 R71 R72 R74 R76-R78 R80-R90 = CRCW040249R9FKED: RES, 49.9, 1%, 0.063 W, 0402; Manufacturer: Vishay-Dale; CompType: Resistor; Value: 49.9; Value_Code: 49R9; Tolerance_%: 1; Power_W: 0.063; Value2: 0.063W; VDC_V: 50; TempCo: 100 ppm/C; SizeArea_mm2: 0.5; SizeZ_mm: 0.6; EIA_Code: E96; U/M: EA; AEC Category: Q200
R69 = RCG060310K0FKEA: as R32 on sheet J6Entry
R70 = RC0603FR-07100KL: RES, 100 k, 1%, 0.1 W, 0603; Manufacturer: Yageo America; CompType: Resistor; Value: 100k; Res_ohm: 100000; Tolerance_%: 1; Power_W: 0.1; Value2: 0.1W; VDC_V: 150; TempCo: 200 ppm/C; SizeArea_mm2: 1.28; SizeX_mm: 1.6; SizeY_mm: 0.8; EIA_Code: E96; U/M: EA; AEC Category: Q200
R73 = CRCW060310R0FKEA: as R38 on sheet J6Entry
R75 R79 = CRCW060310K0FKEA: RES, 10.0 k, 1%, 0.1 W, 0603; Manufacturer: Vishay-Dale; CompType: Resistor; Value: 10.0k; Res_ohm: 10000; Value_Code: 10k0; Tolerance_%: 1; Power_W: 0.1; Value2: 0.1W; VDC_V: 75; TempCo: 100 ppm/C; SizeArea_mm2: 1.28; SizeX_mm: 1.6; SizeY_mm: 0.8; EIA_Code: E96; U/M: EA; AEC Category: Q200
U13 = DRA710CBD: as U13 on sheet DIG PWR
U19 = TPS51200QDRCRQ1: Single Output Automotive LDO, 3 A, 2.3 to 3.5 V Input, with DDR Termination, 10-pin SON (DRC), -40 to 125 degC, Green (RoHS & no Sb/Br); Manufacturer: Texas Instruments; Alternate PartNumber: Equivalent; Iout(Max)(A): 3; Iq(Typ)(mA): 0.5; Power Good: TRUE; SubFamily: Single Channel LDO; Vin(Max)(V): 3.5; Vin(Min)(V): 2.3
